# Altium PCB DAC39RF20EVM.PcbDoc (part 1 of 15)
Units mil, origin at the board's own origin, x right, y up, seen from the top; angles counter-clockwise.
Board outline 6200 x 2716.54 mil, 16 copper layers (Top Layer, L2 GND, L3 PWR, L4 GND, L5 PWR, L6 GND, L7 SIG, L8 GND, L9 GND, L10 SIG, L11 GND, L12 PWR, L13 GND, L14 PWR, L15 GND, Bottom Layer), stack 76.97 mil thick; 766 components, 495 nets, 3414 pads, 2373 vias.
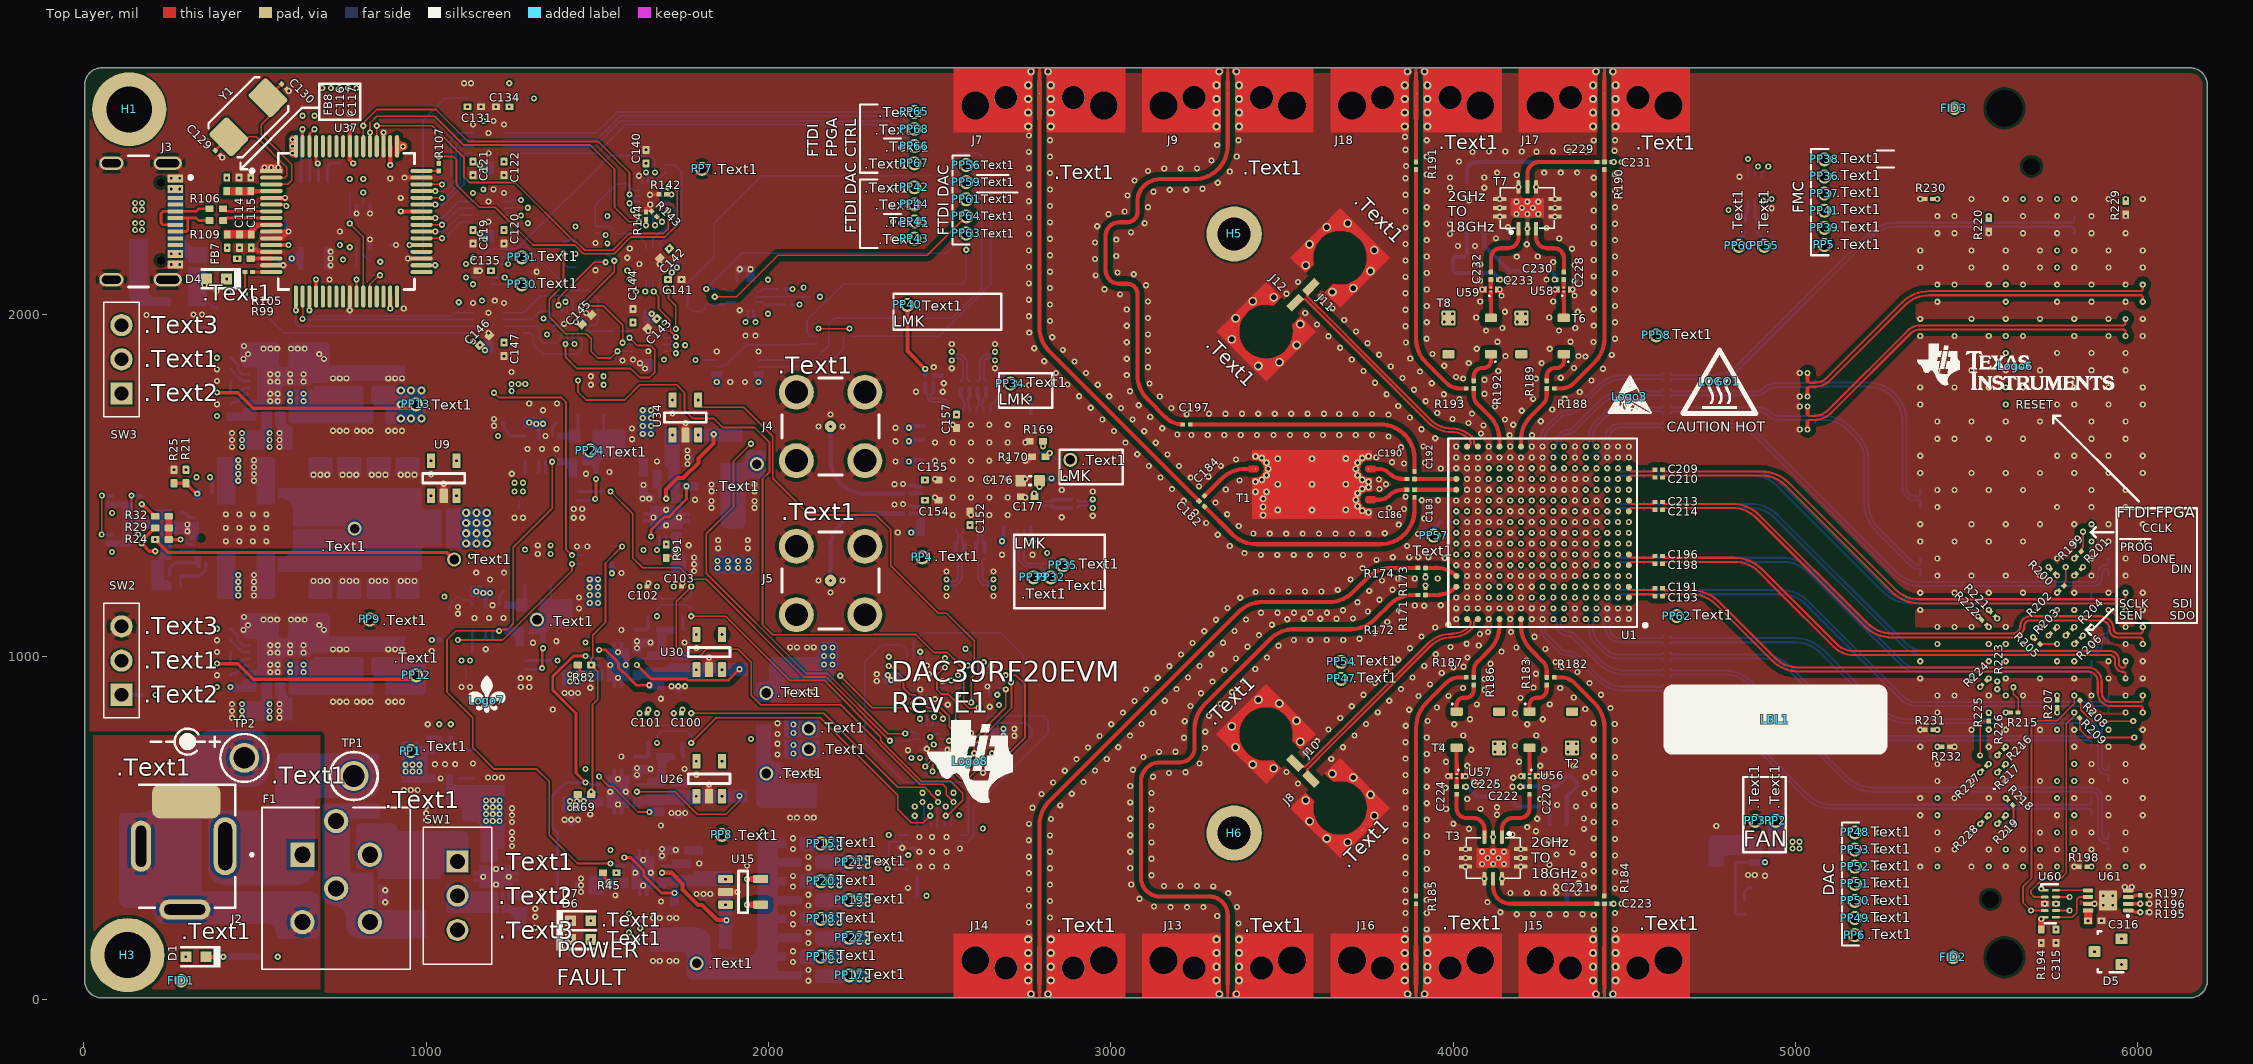
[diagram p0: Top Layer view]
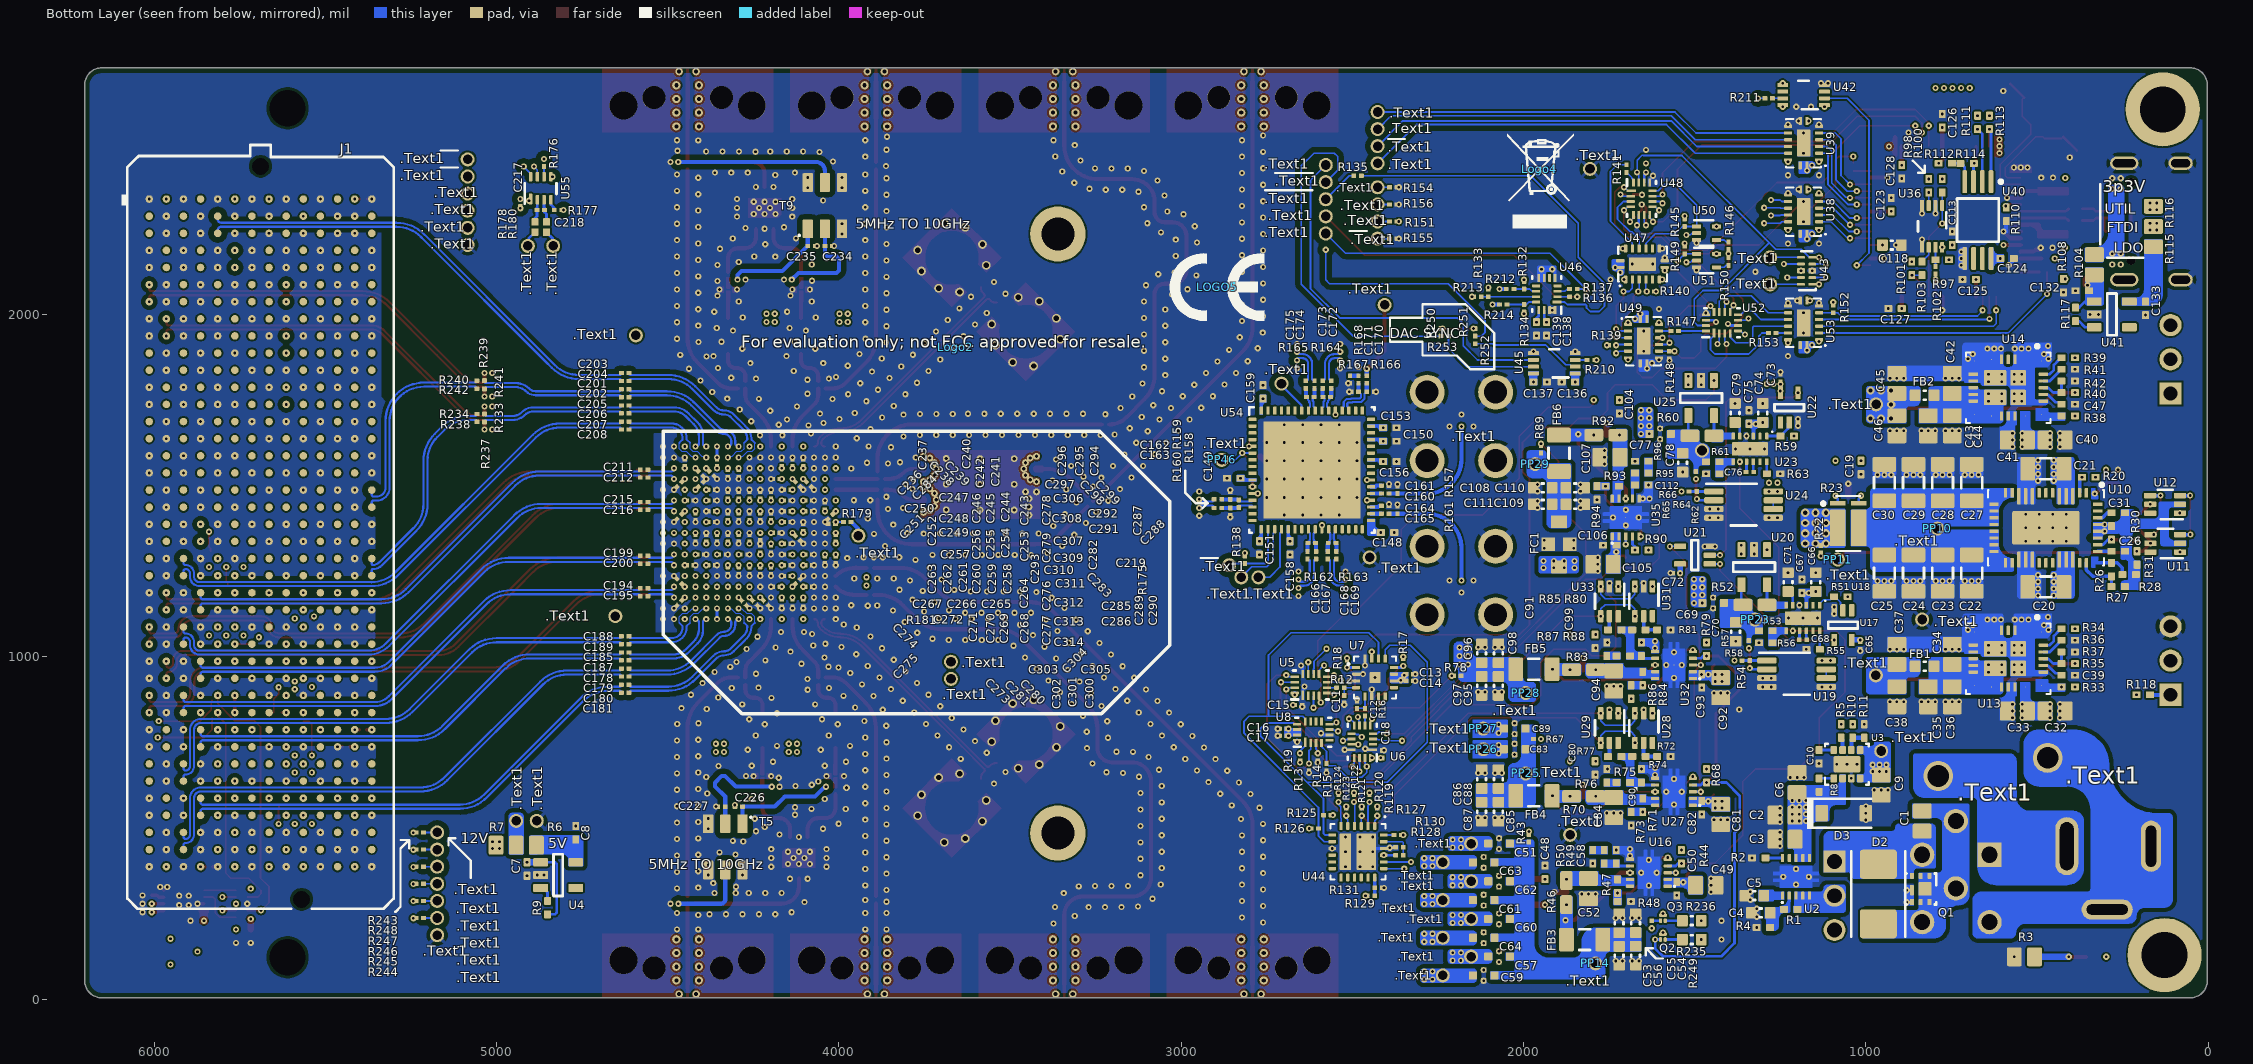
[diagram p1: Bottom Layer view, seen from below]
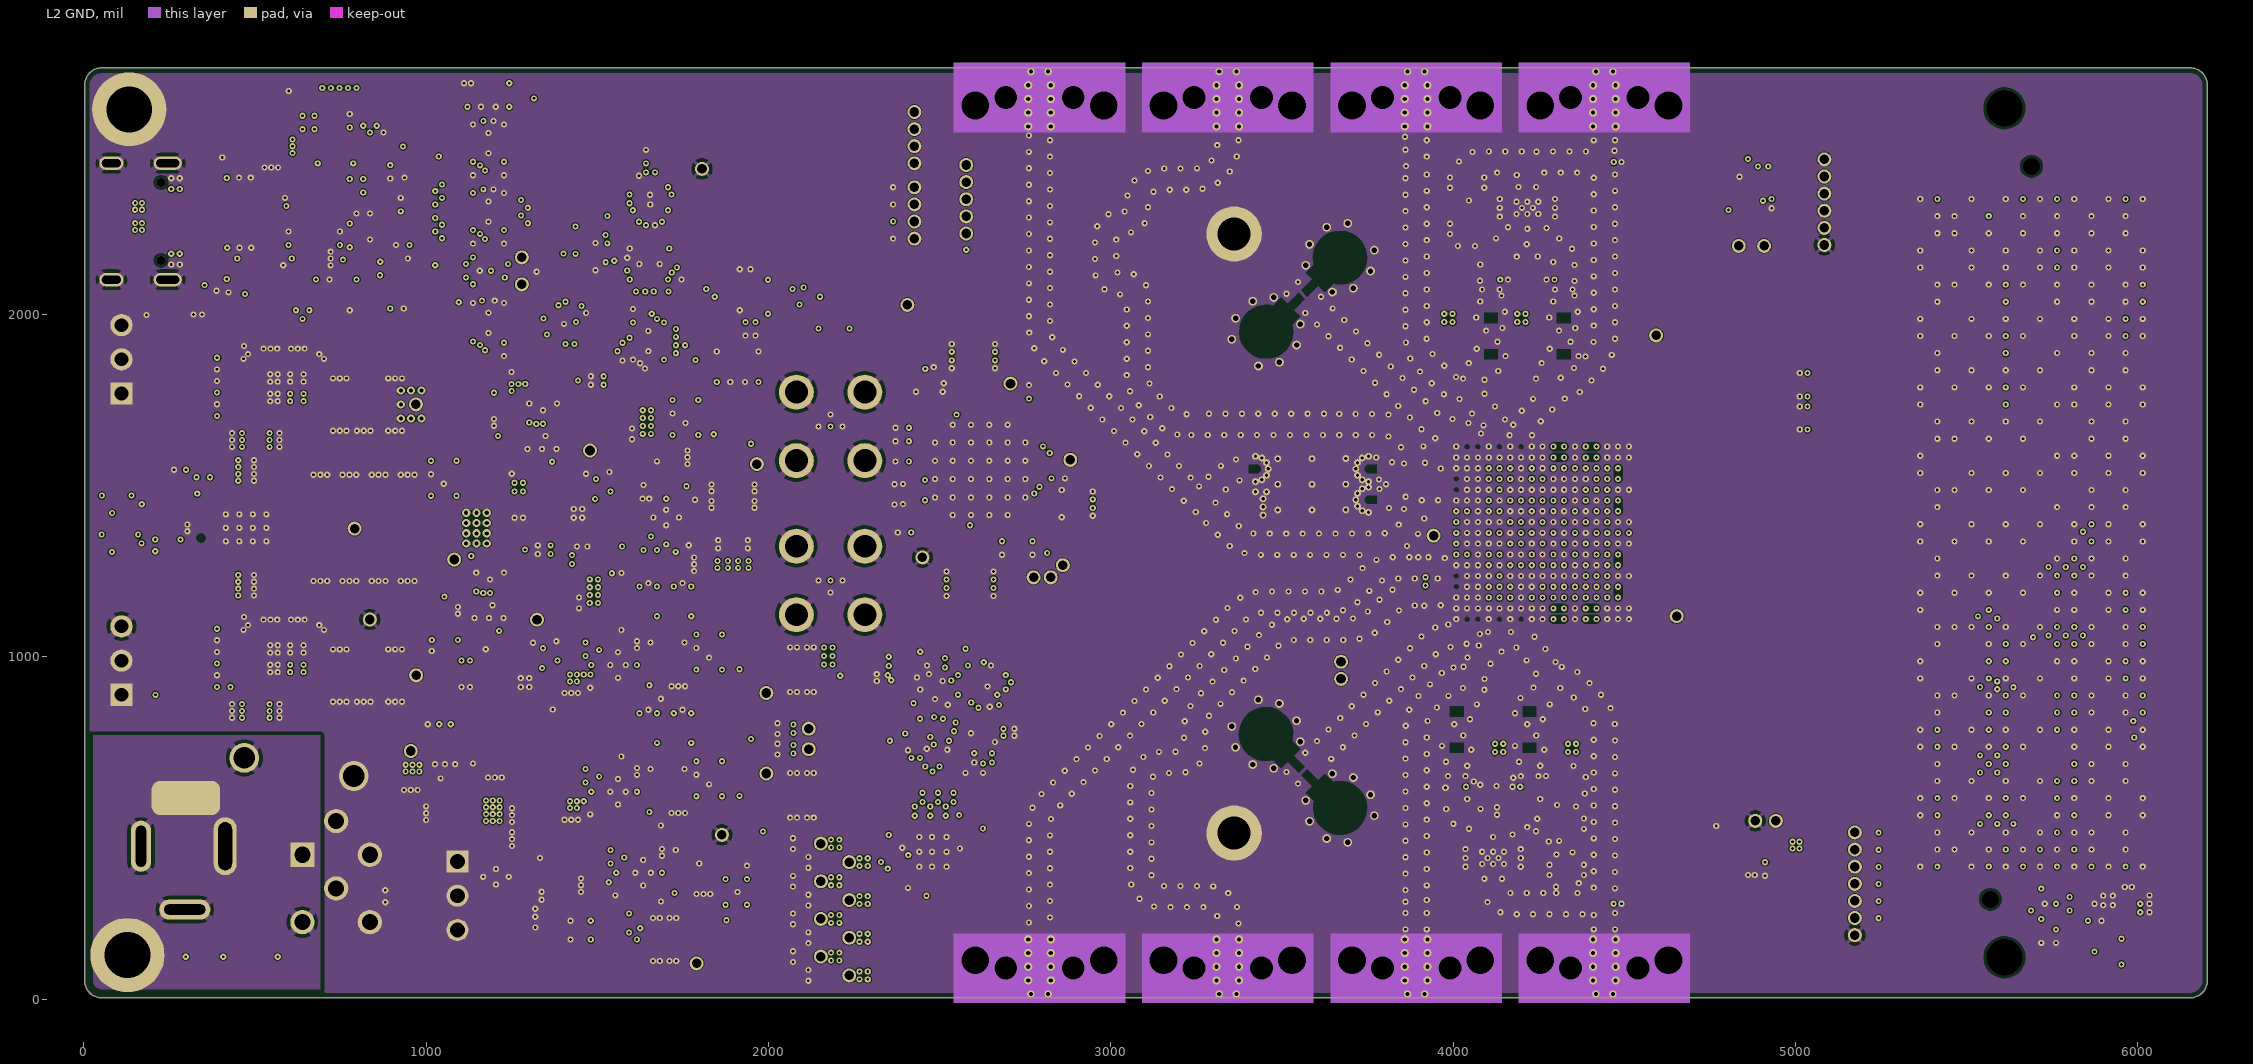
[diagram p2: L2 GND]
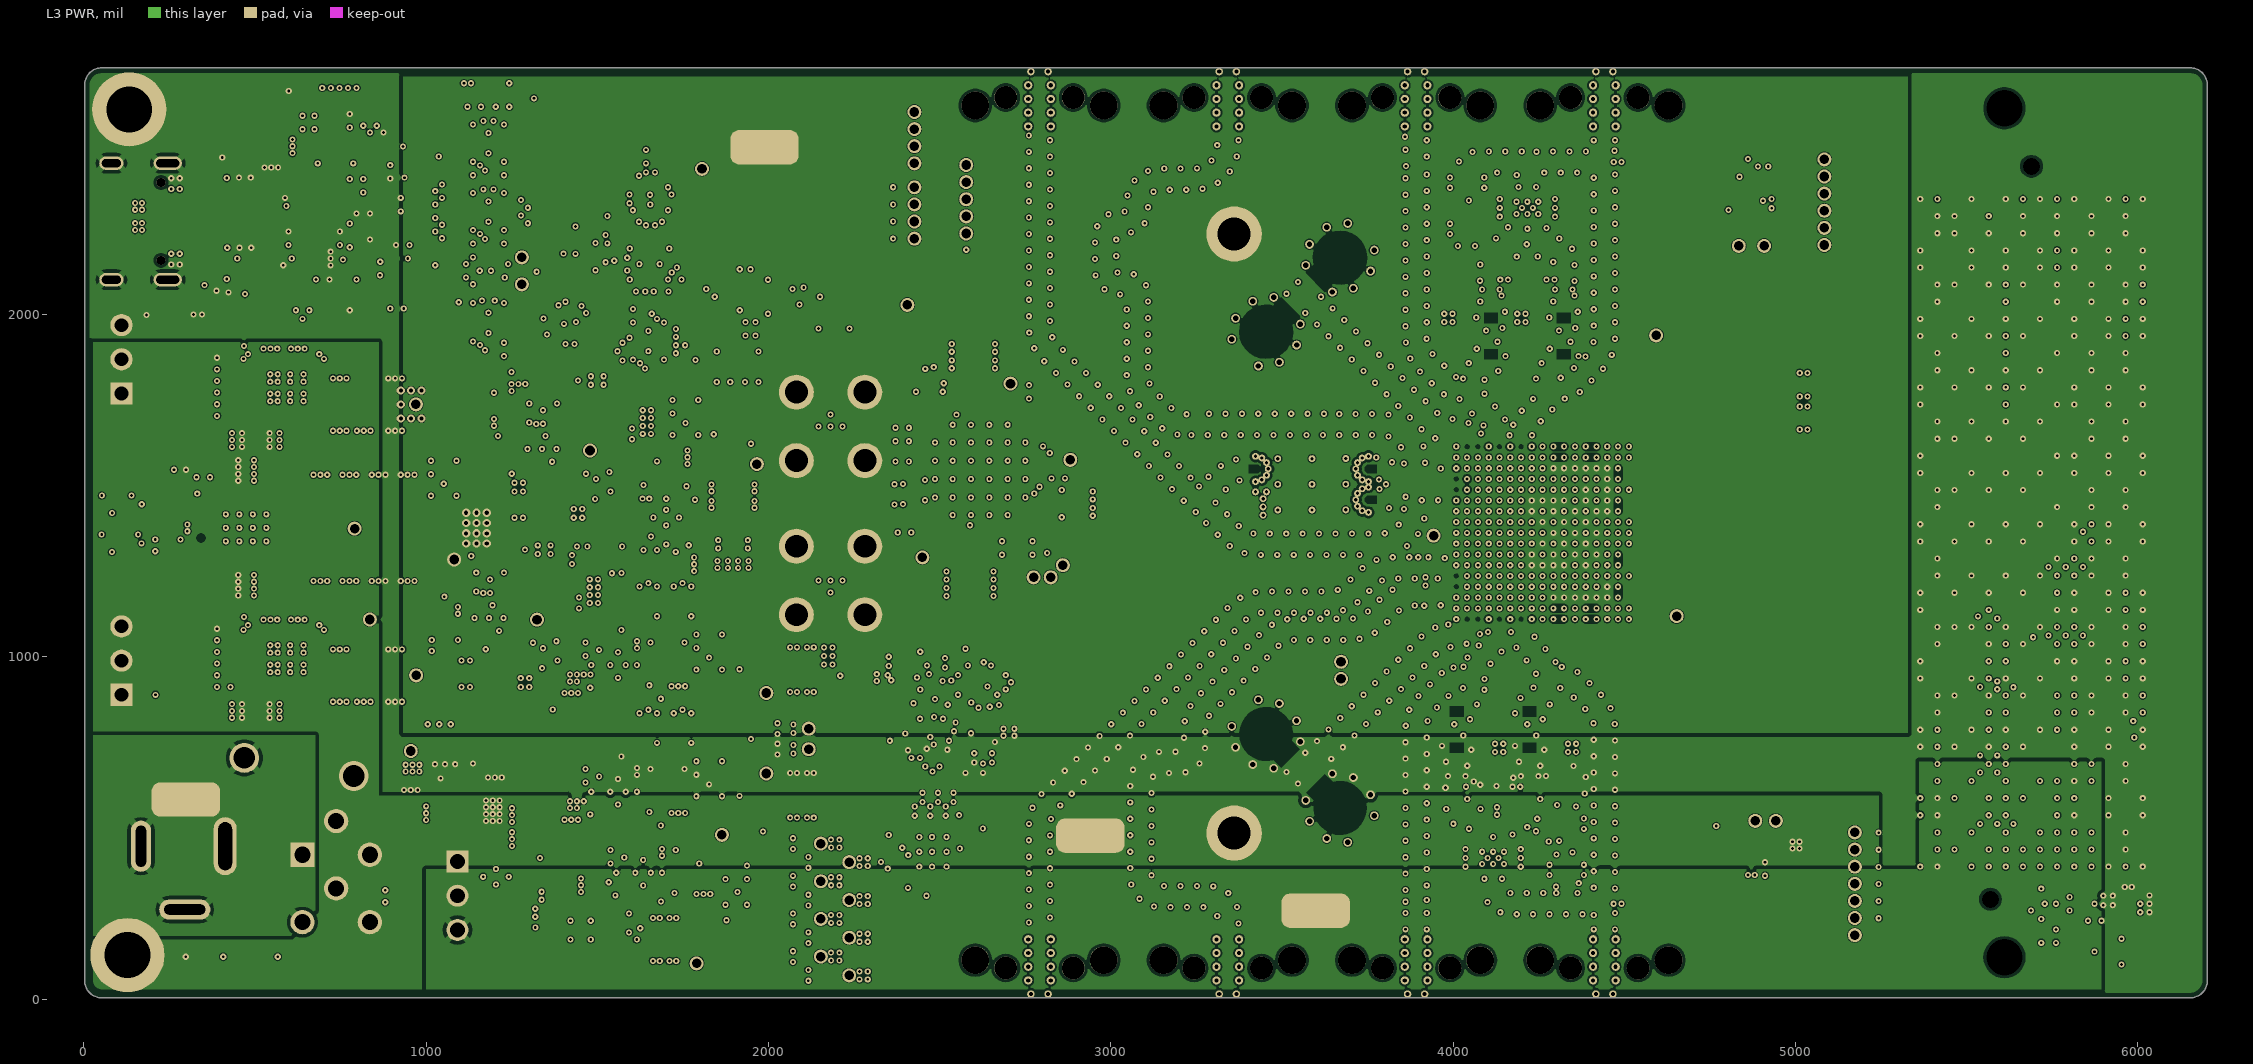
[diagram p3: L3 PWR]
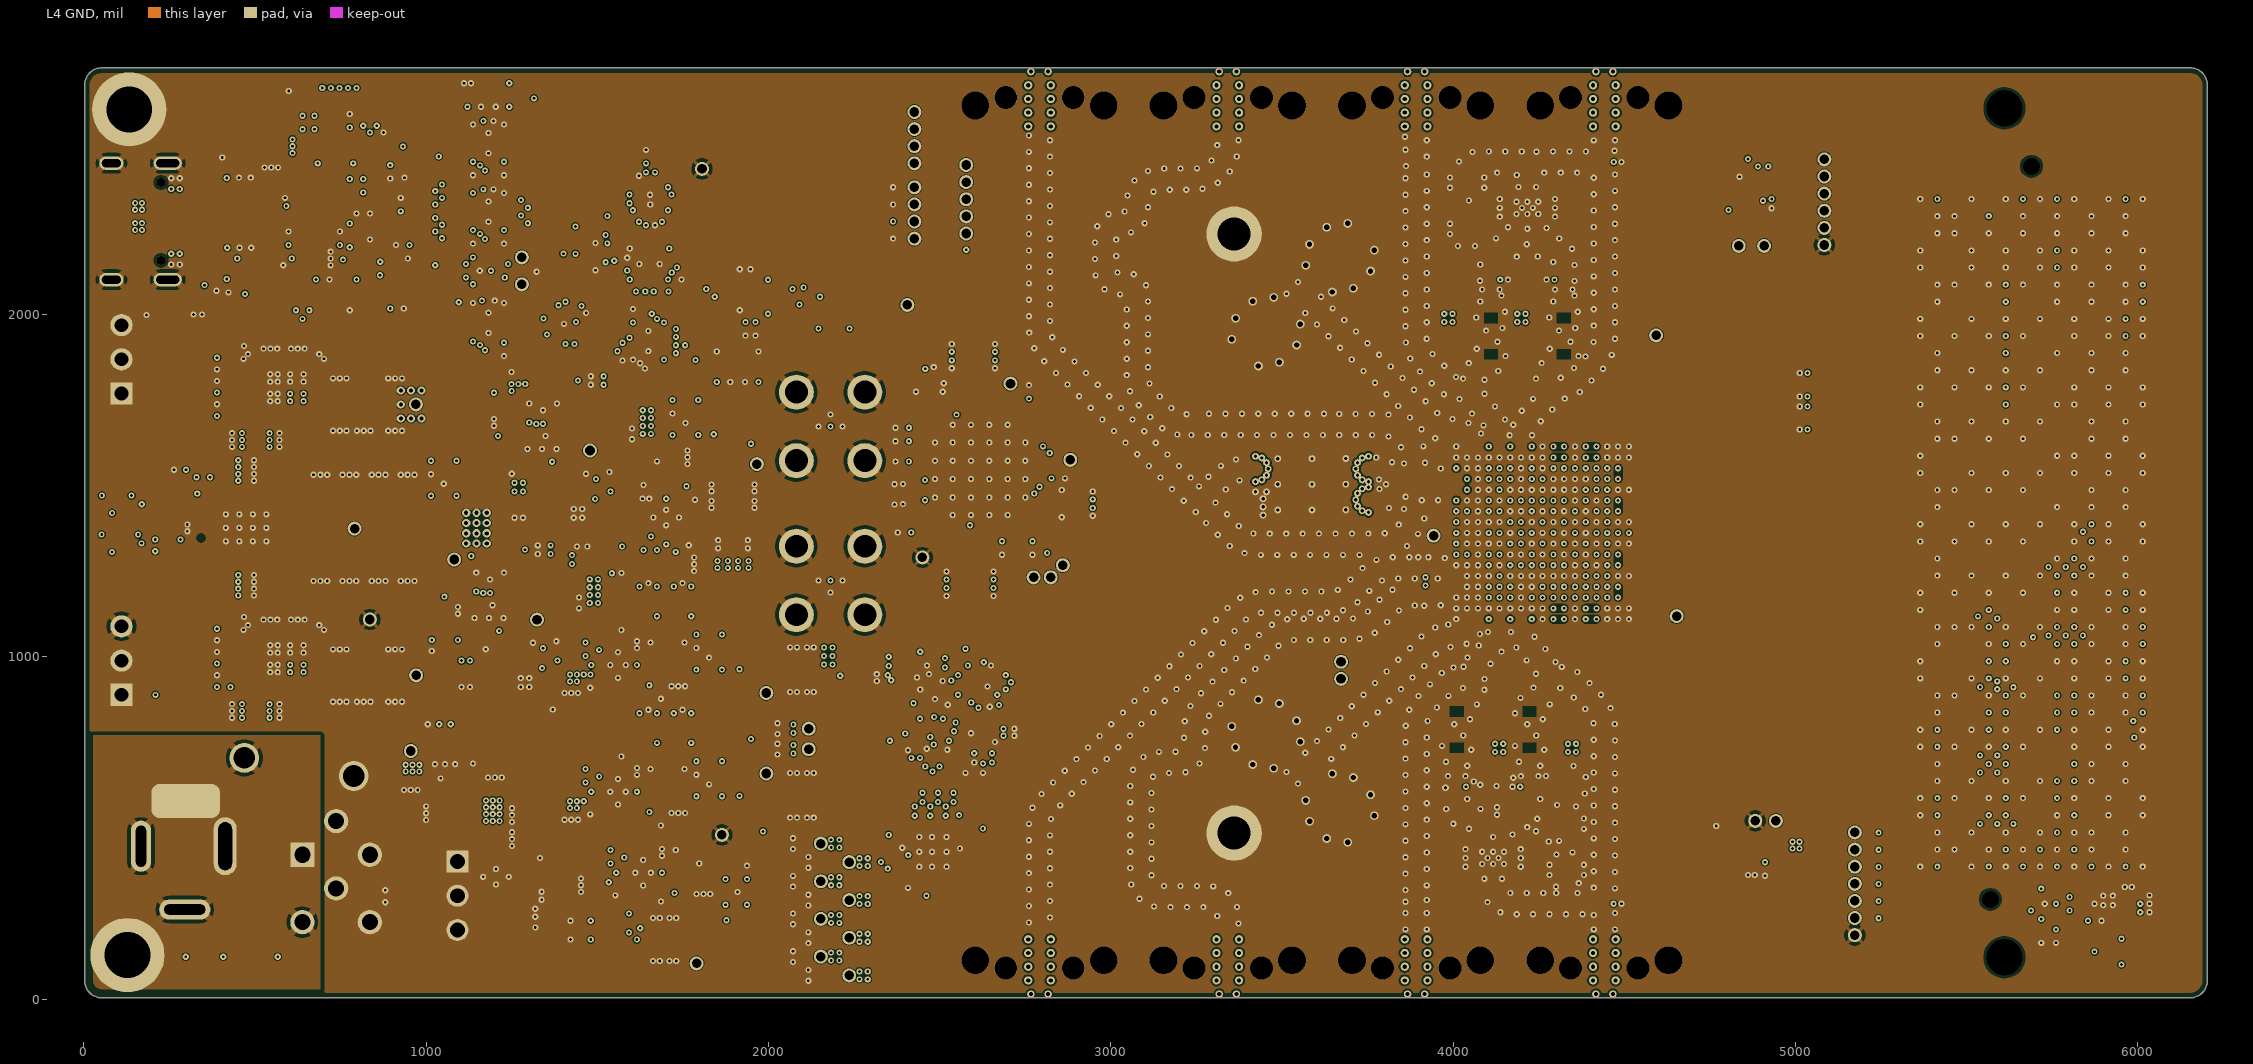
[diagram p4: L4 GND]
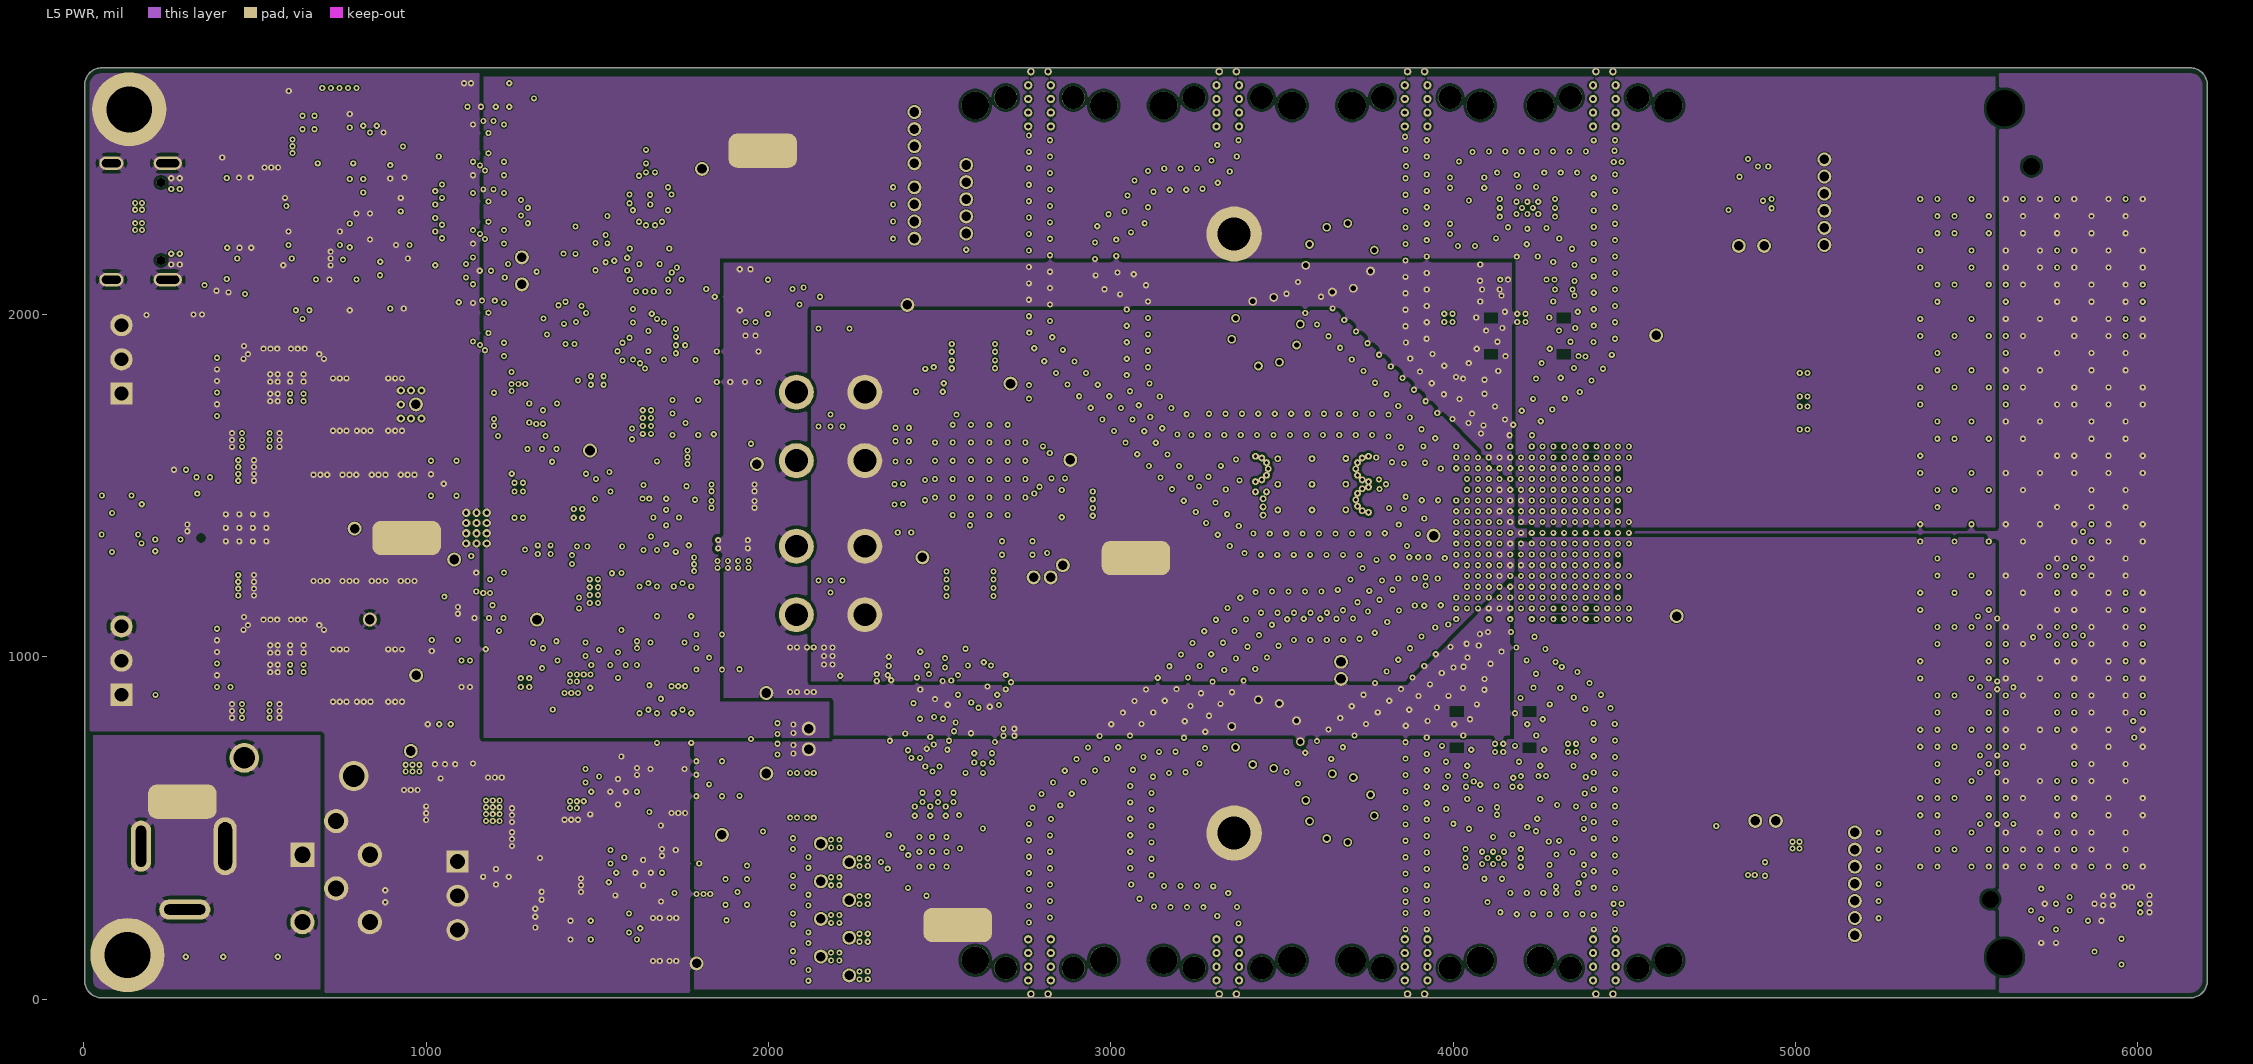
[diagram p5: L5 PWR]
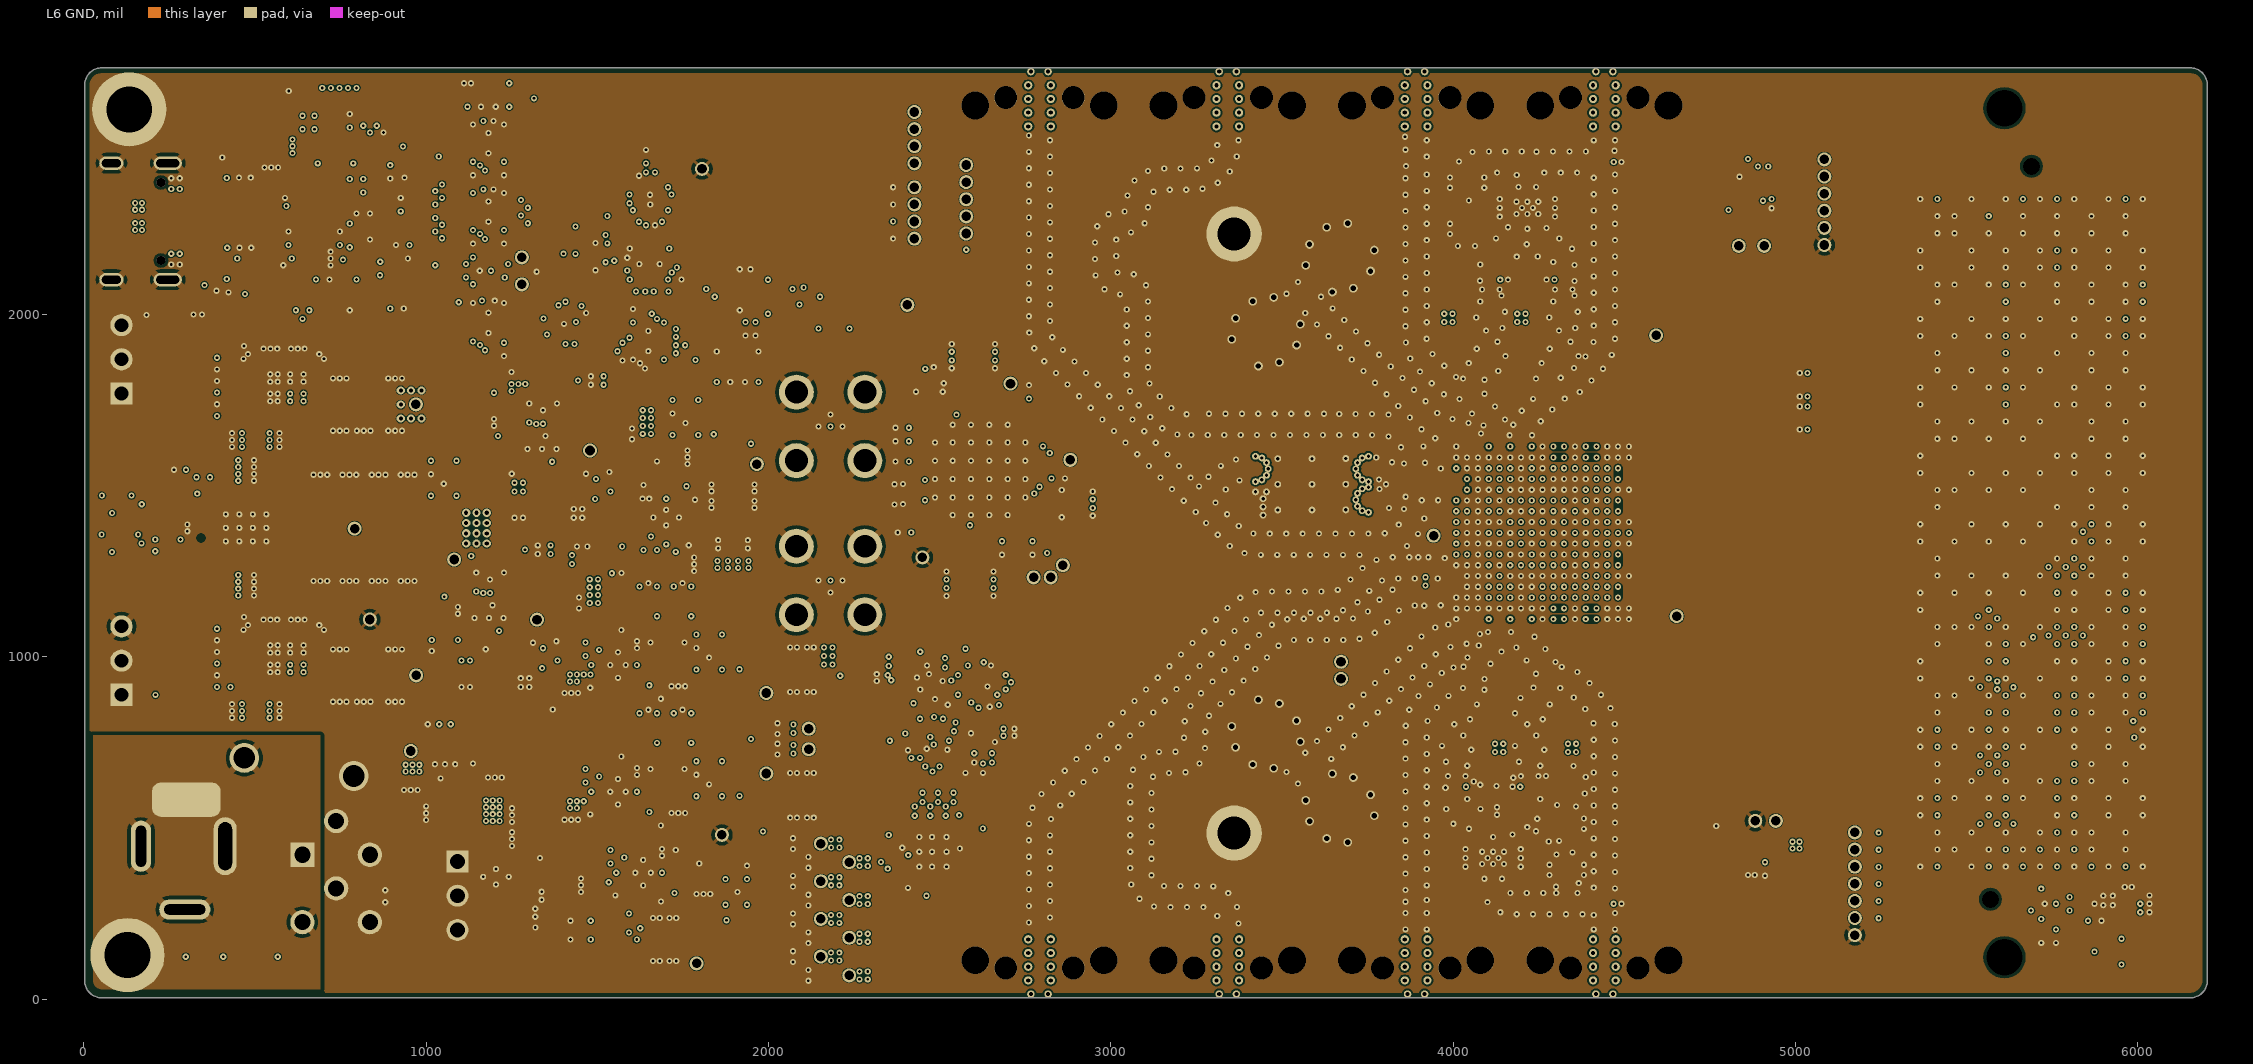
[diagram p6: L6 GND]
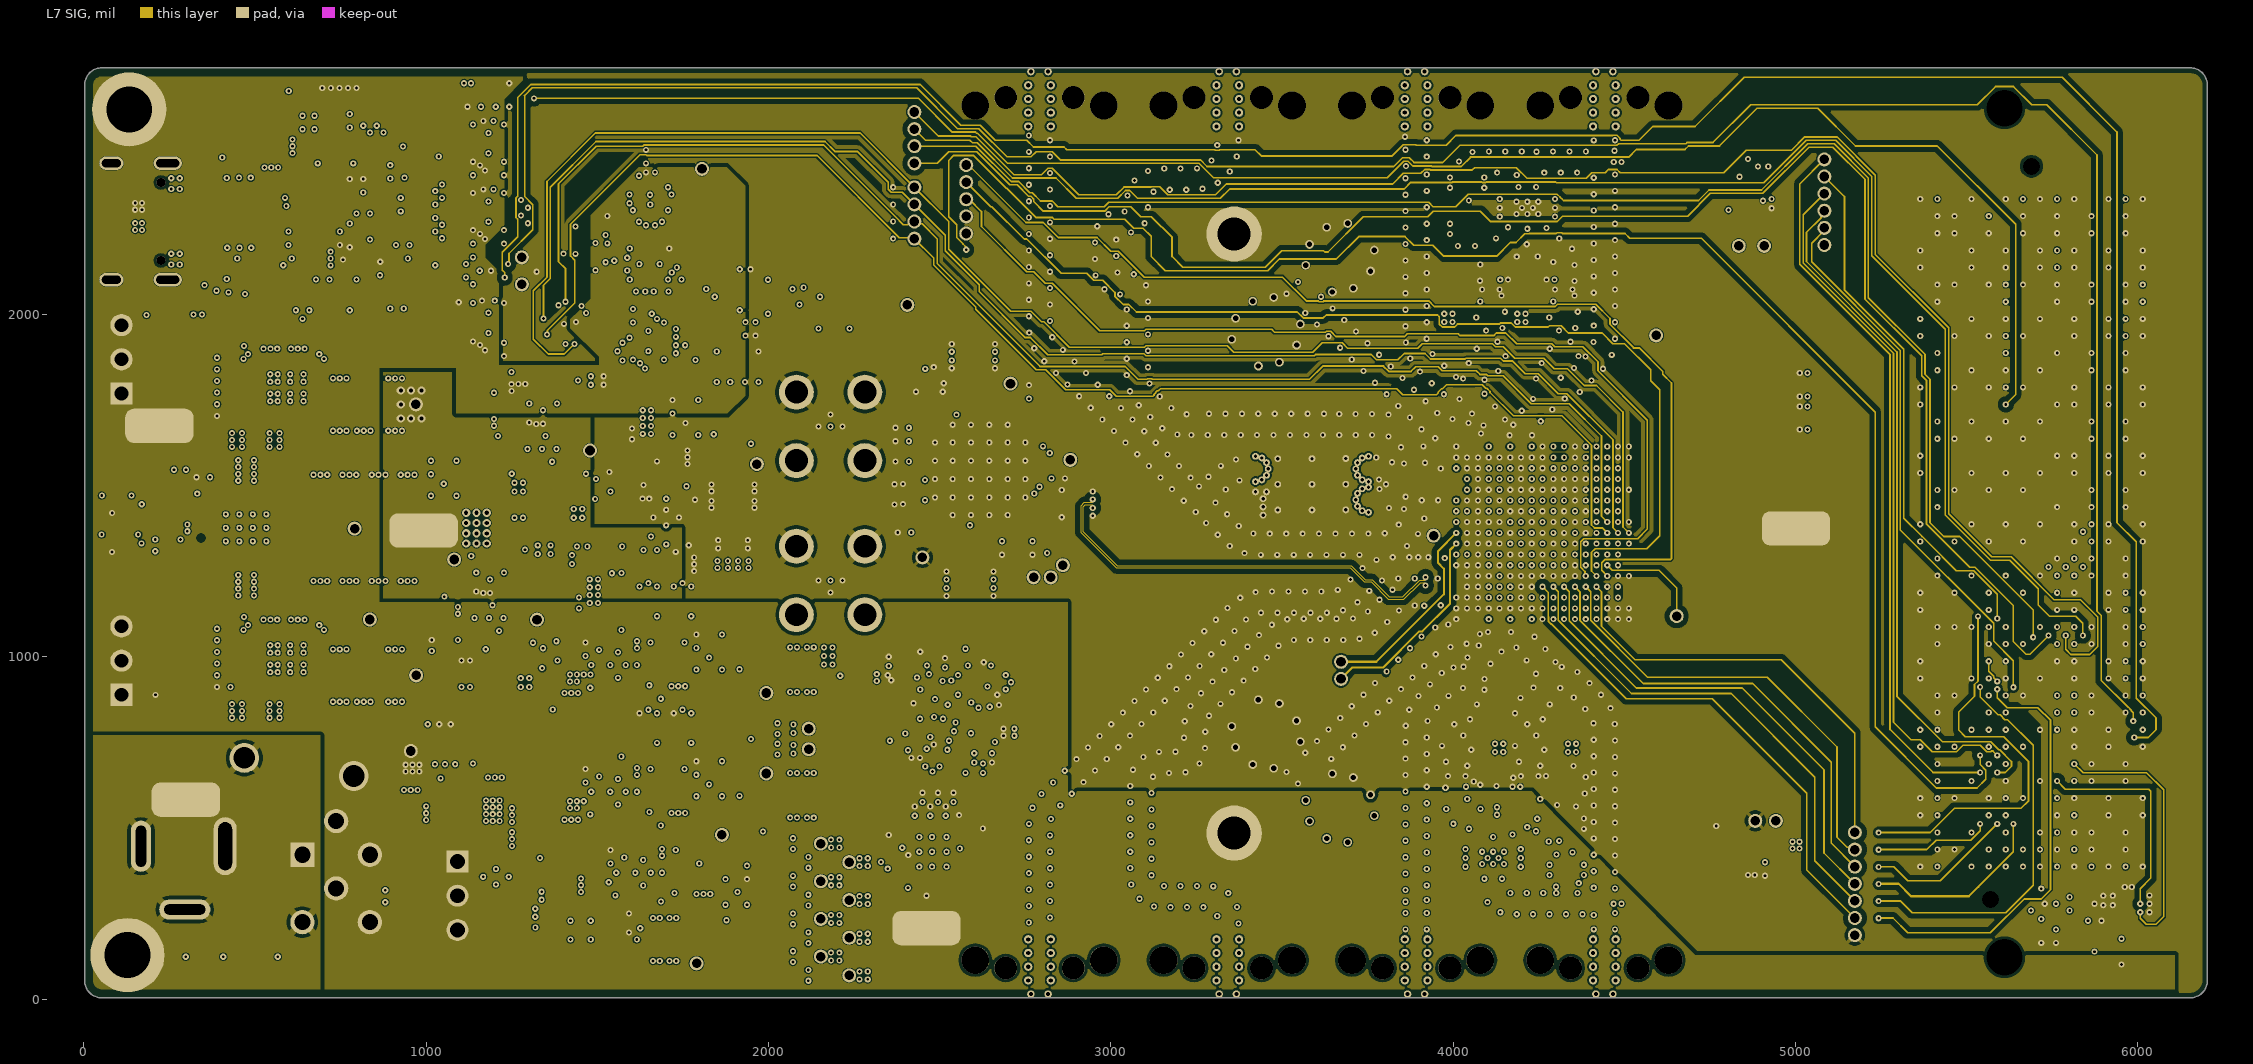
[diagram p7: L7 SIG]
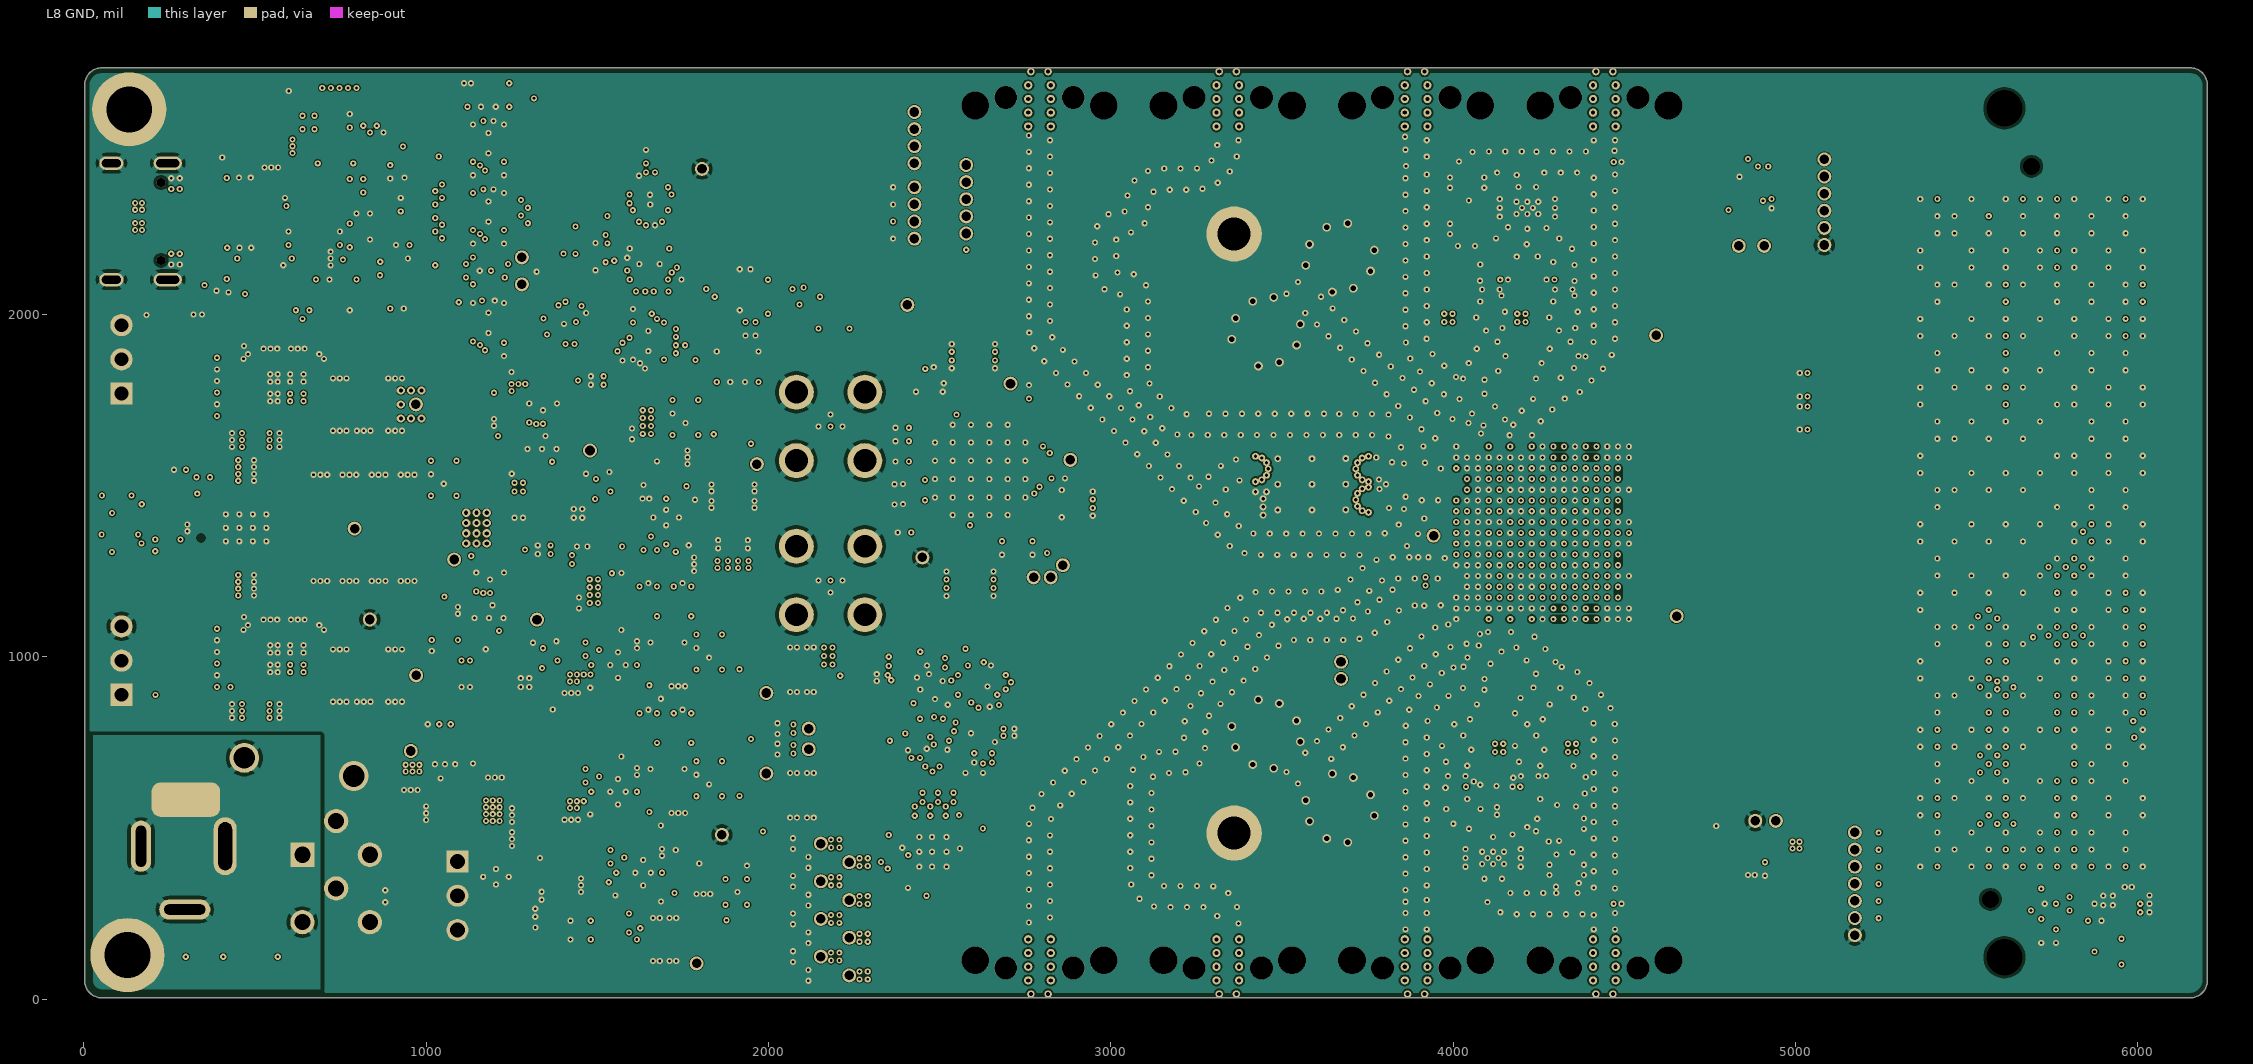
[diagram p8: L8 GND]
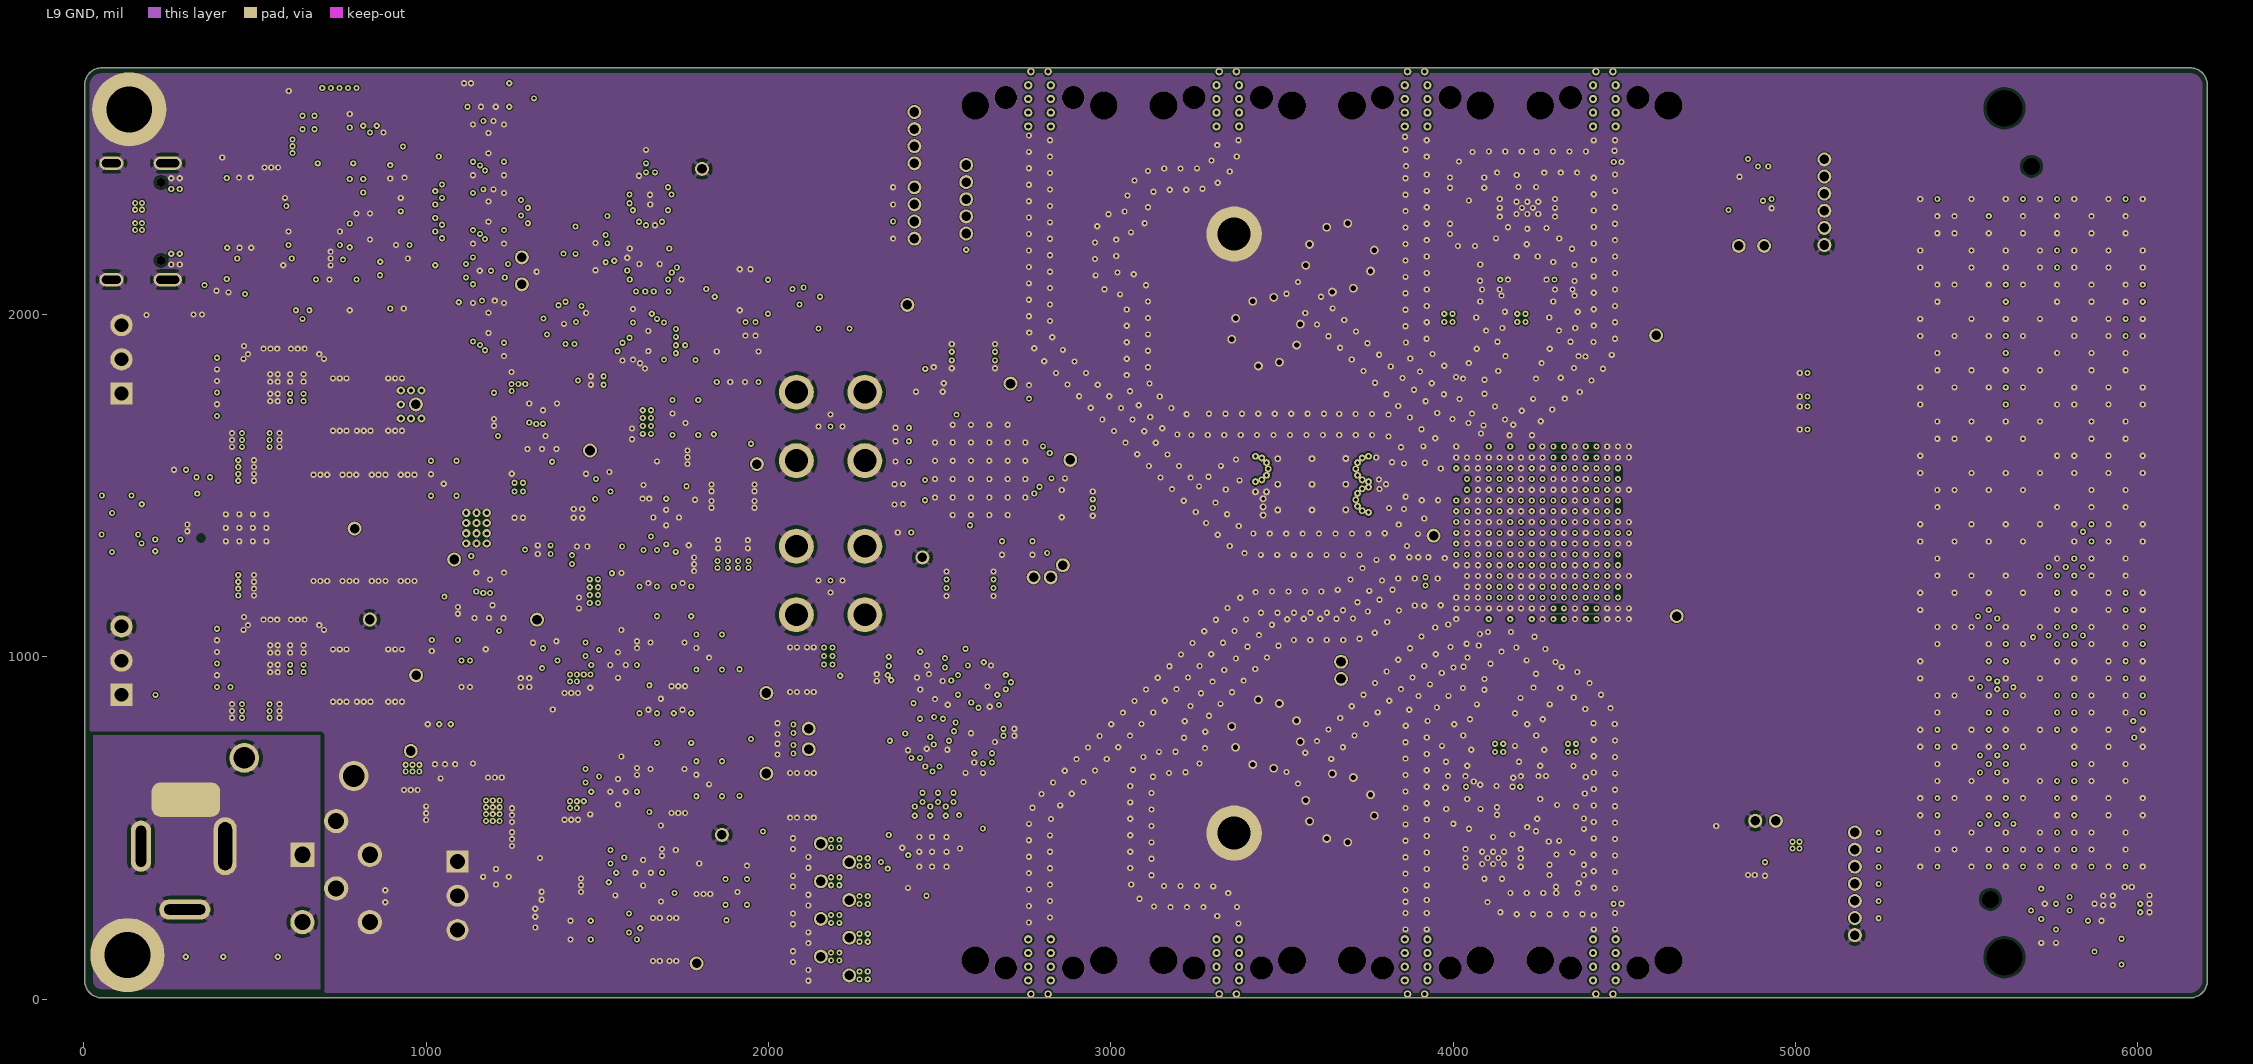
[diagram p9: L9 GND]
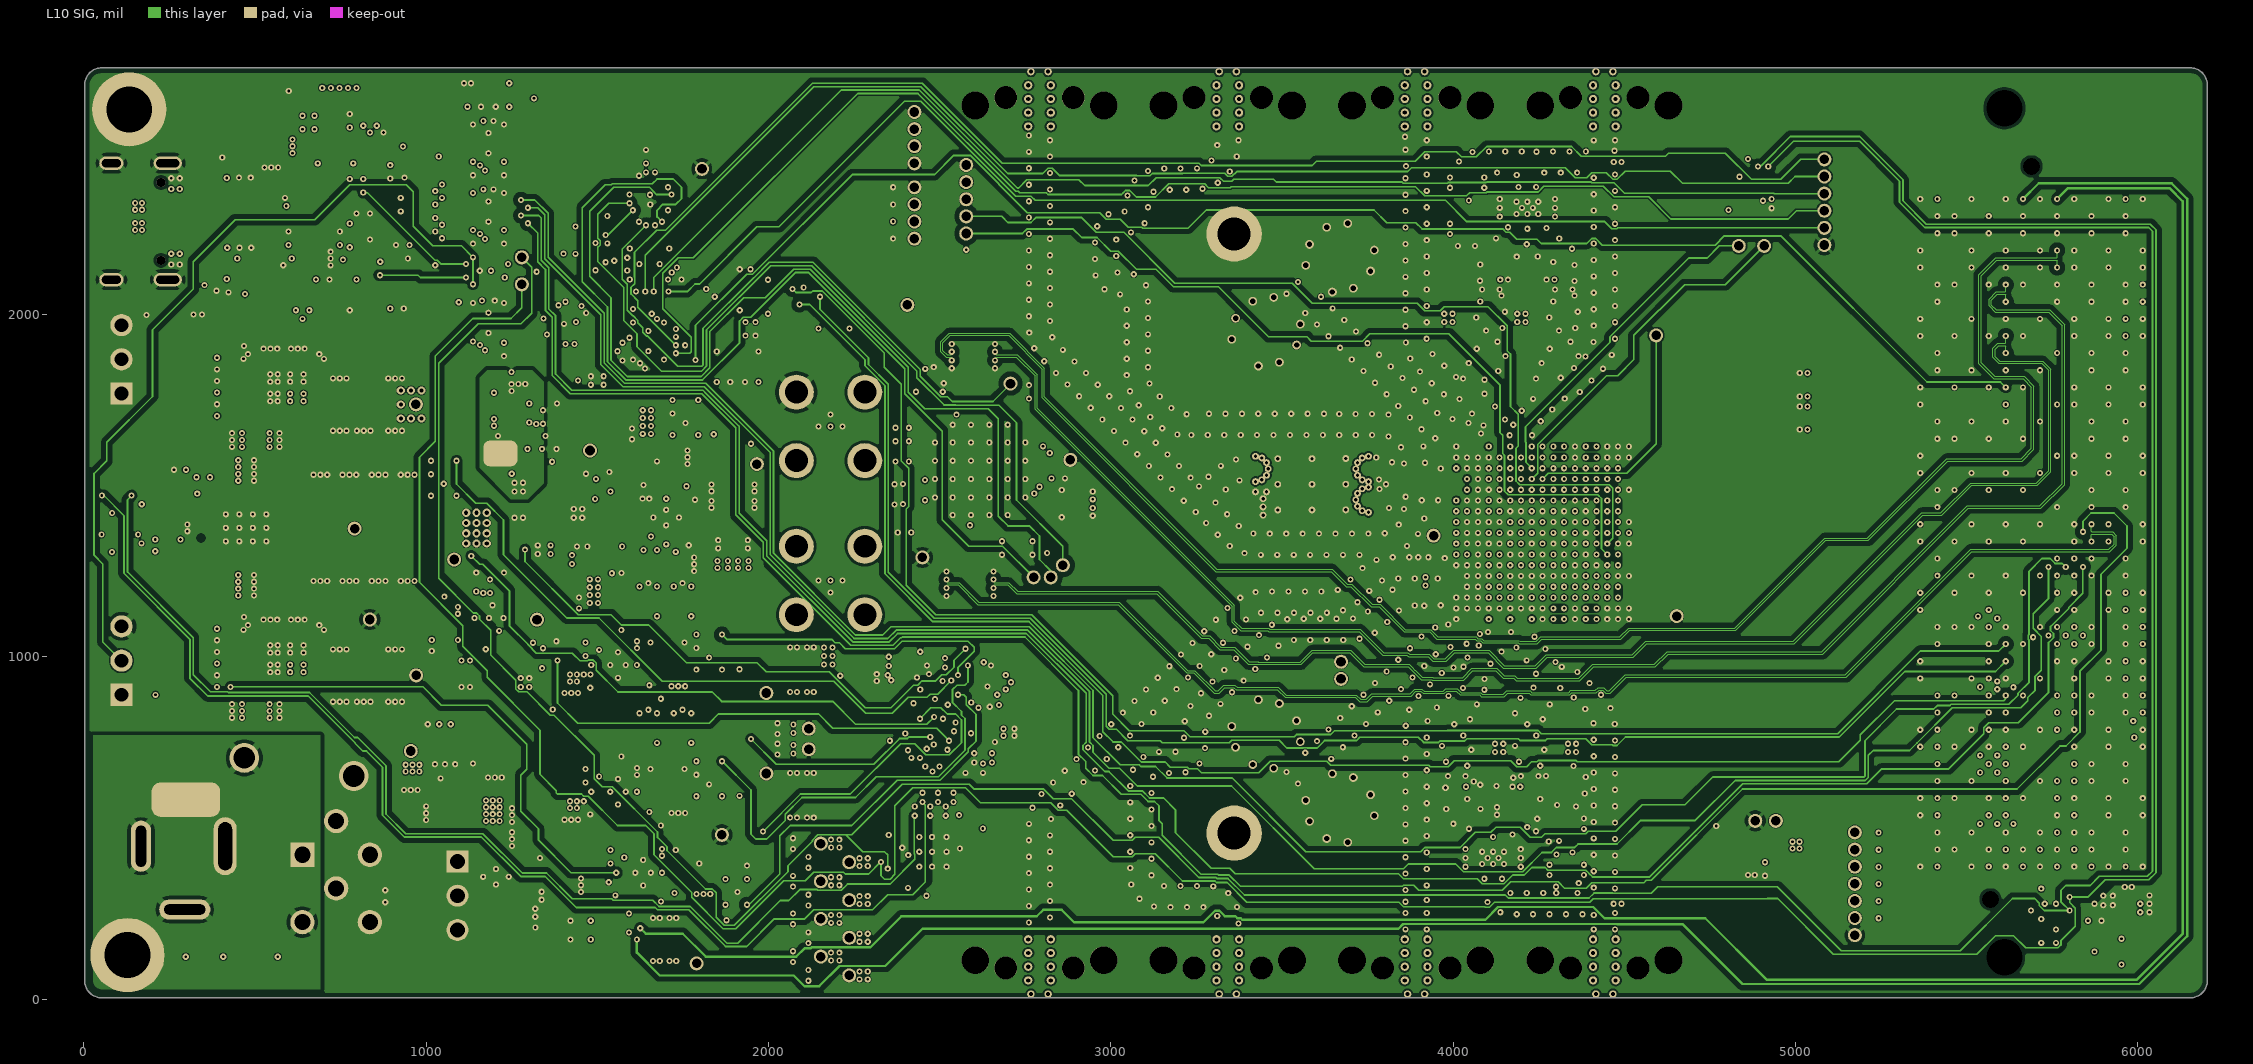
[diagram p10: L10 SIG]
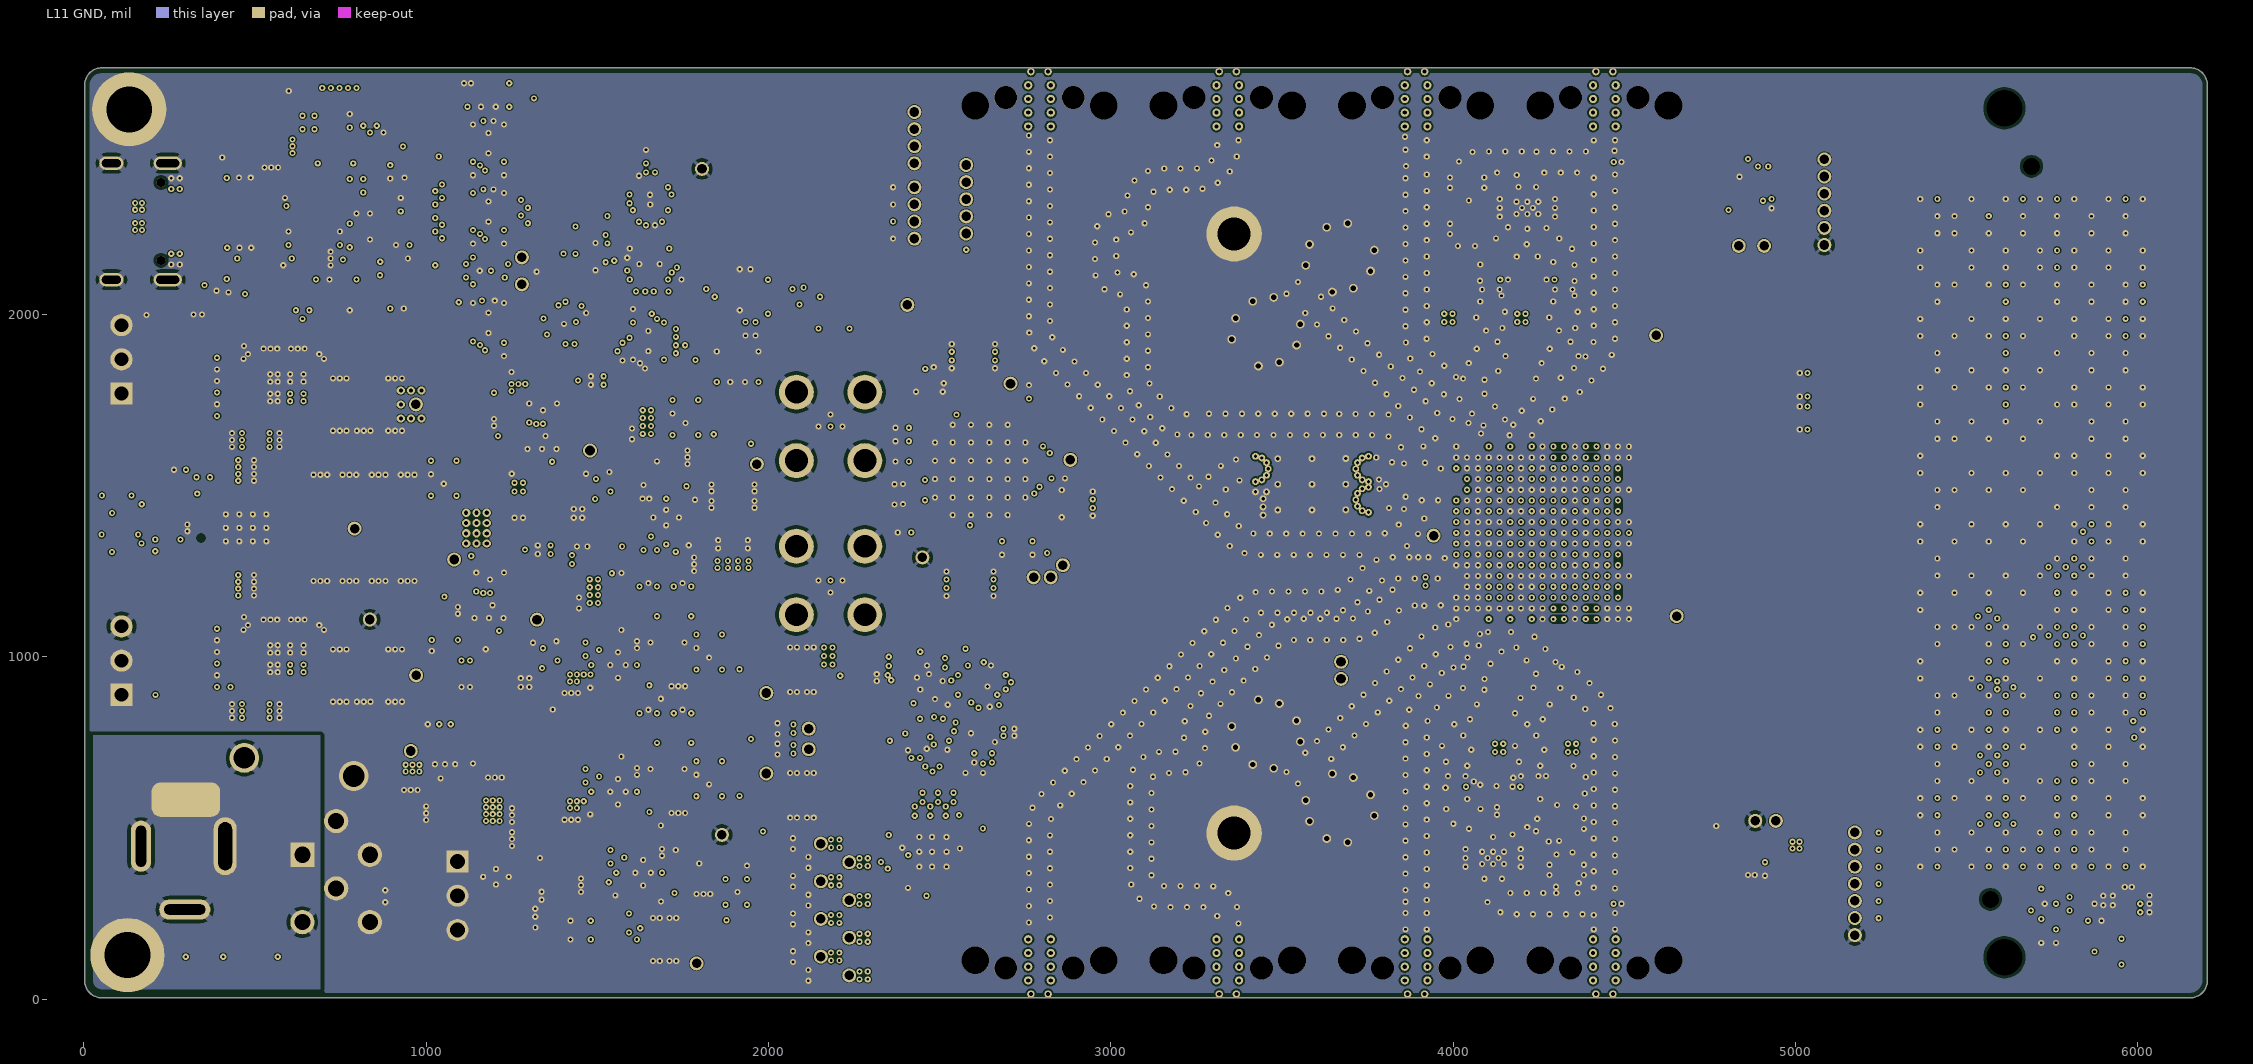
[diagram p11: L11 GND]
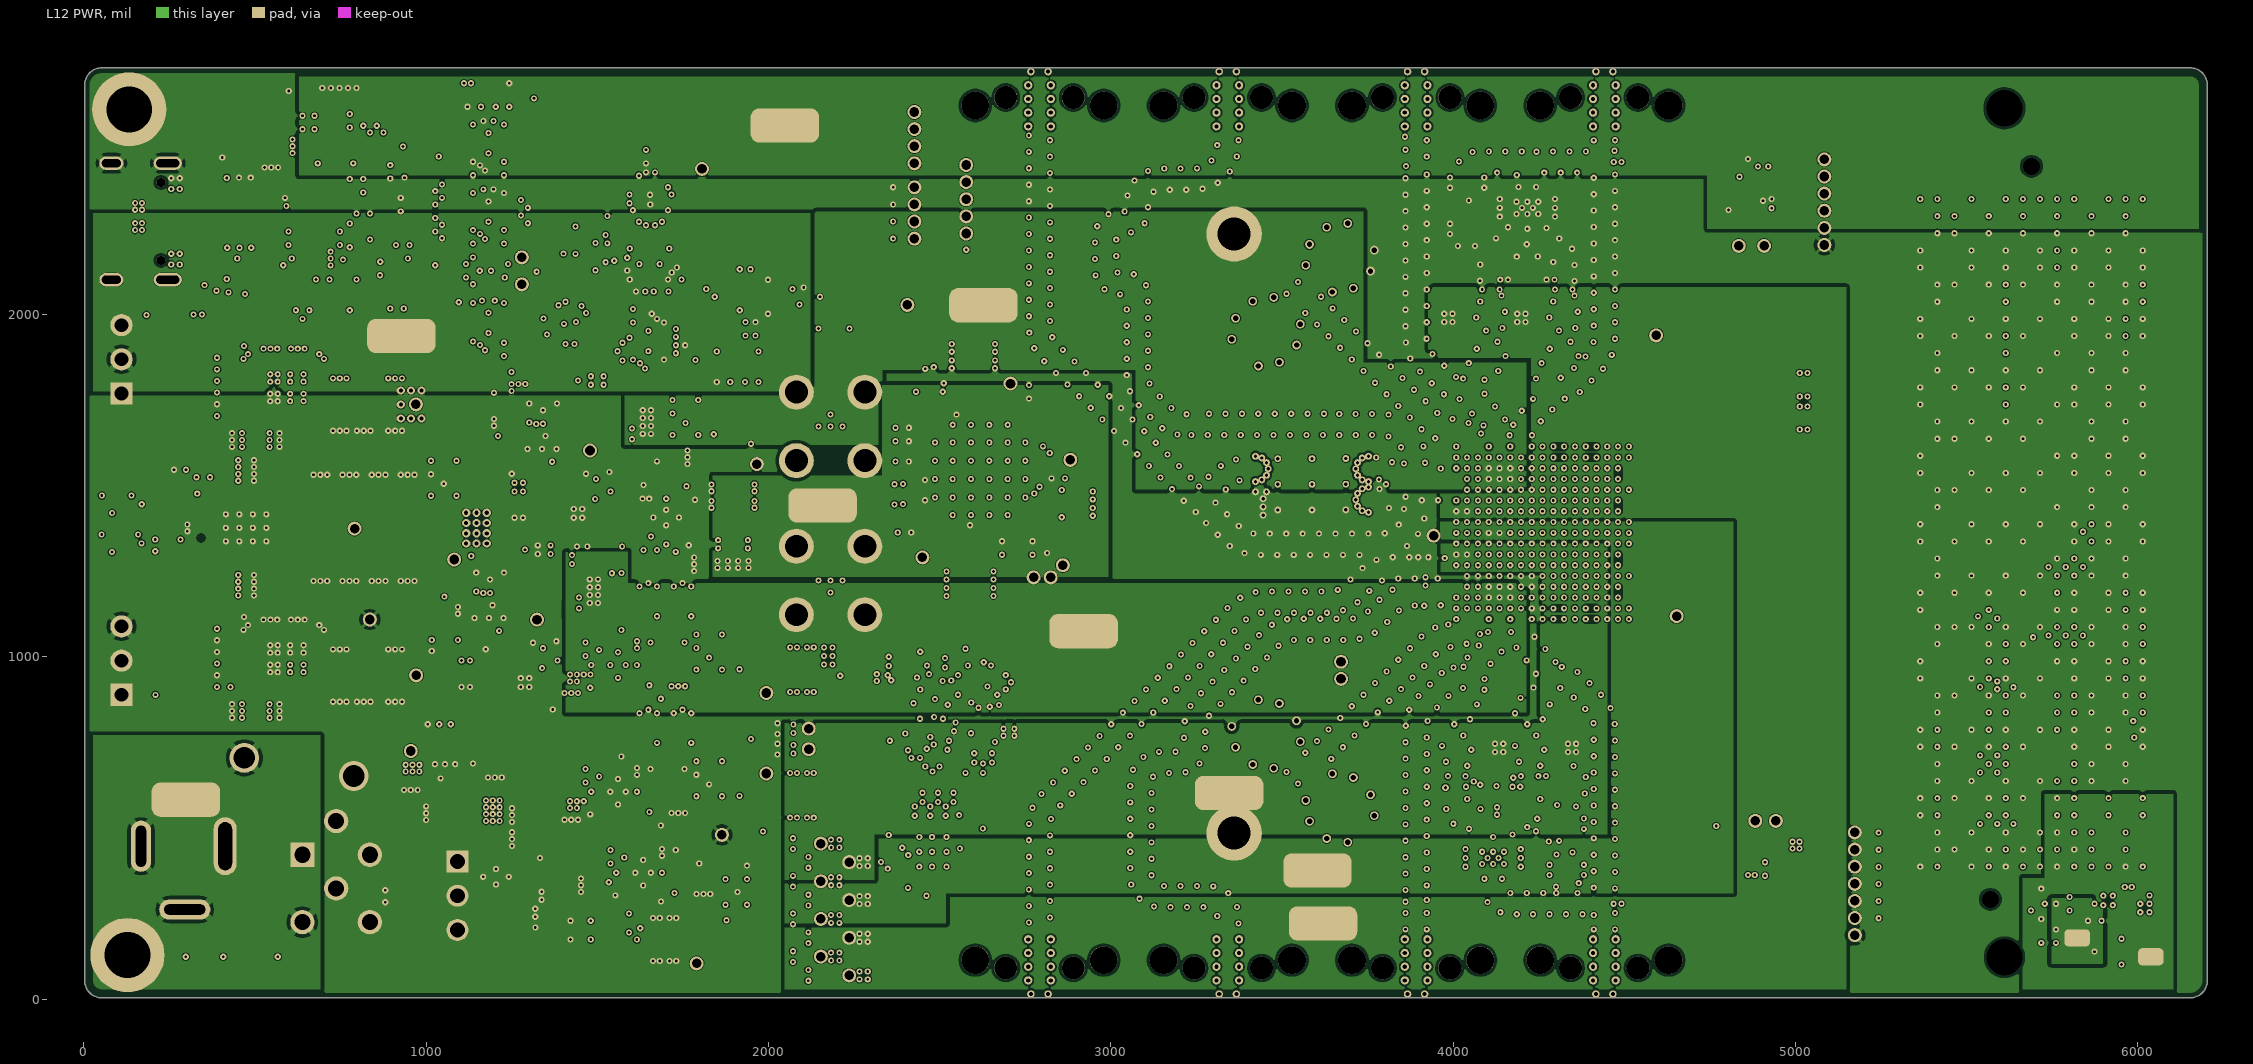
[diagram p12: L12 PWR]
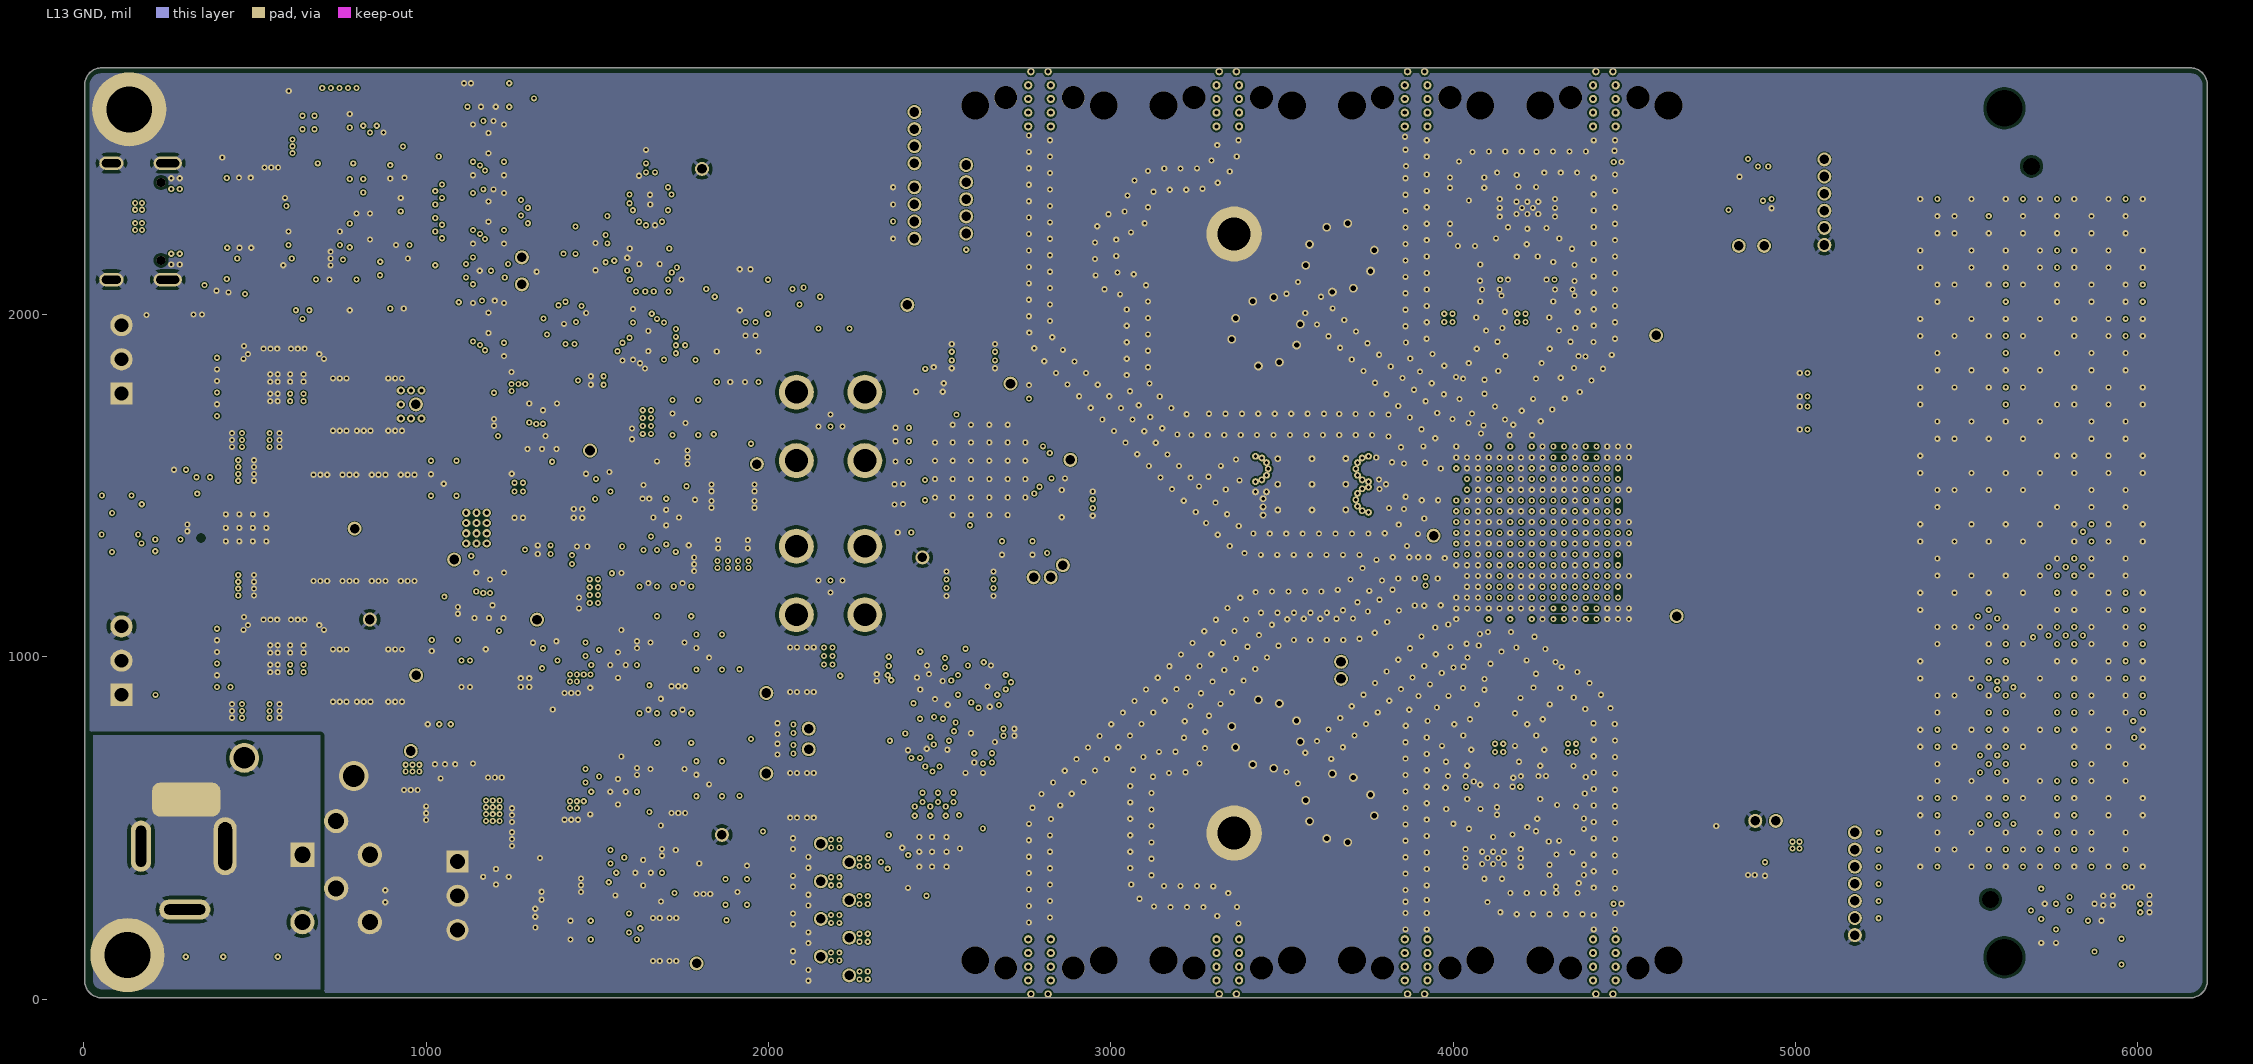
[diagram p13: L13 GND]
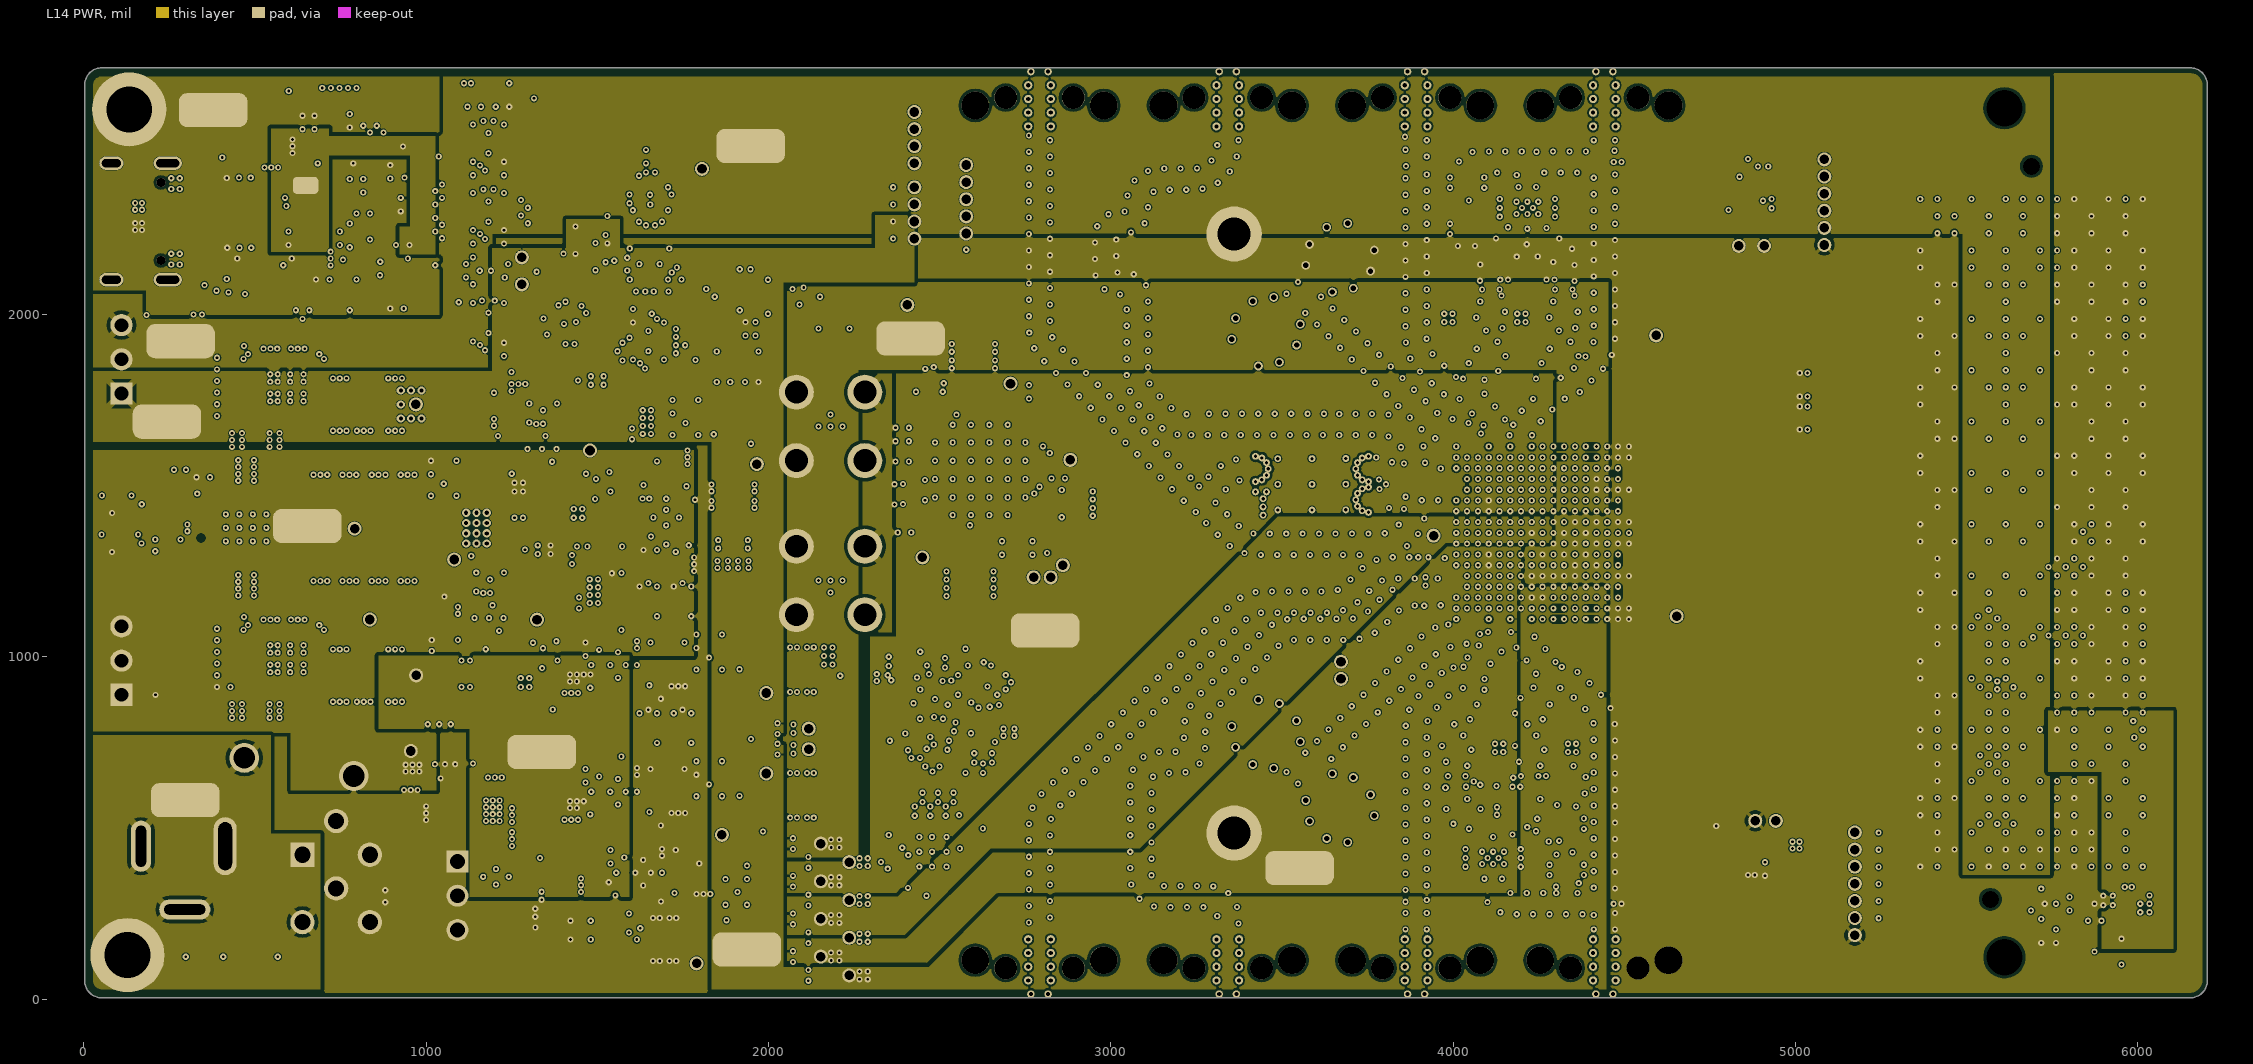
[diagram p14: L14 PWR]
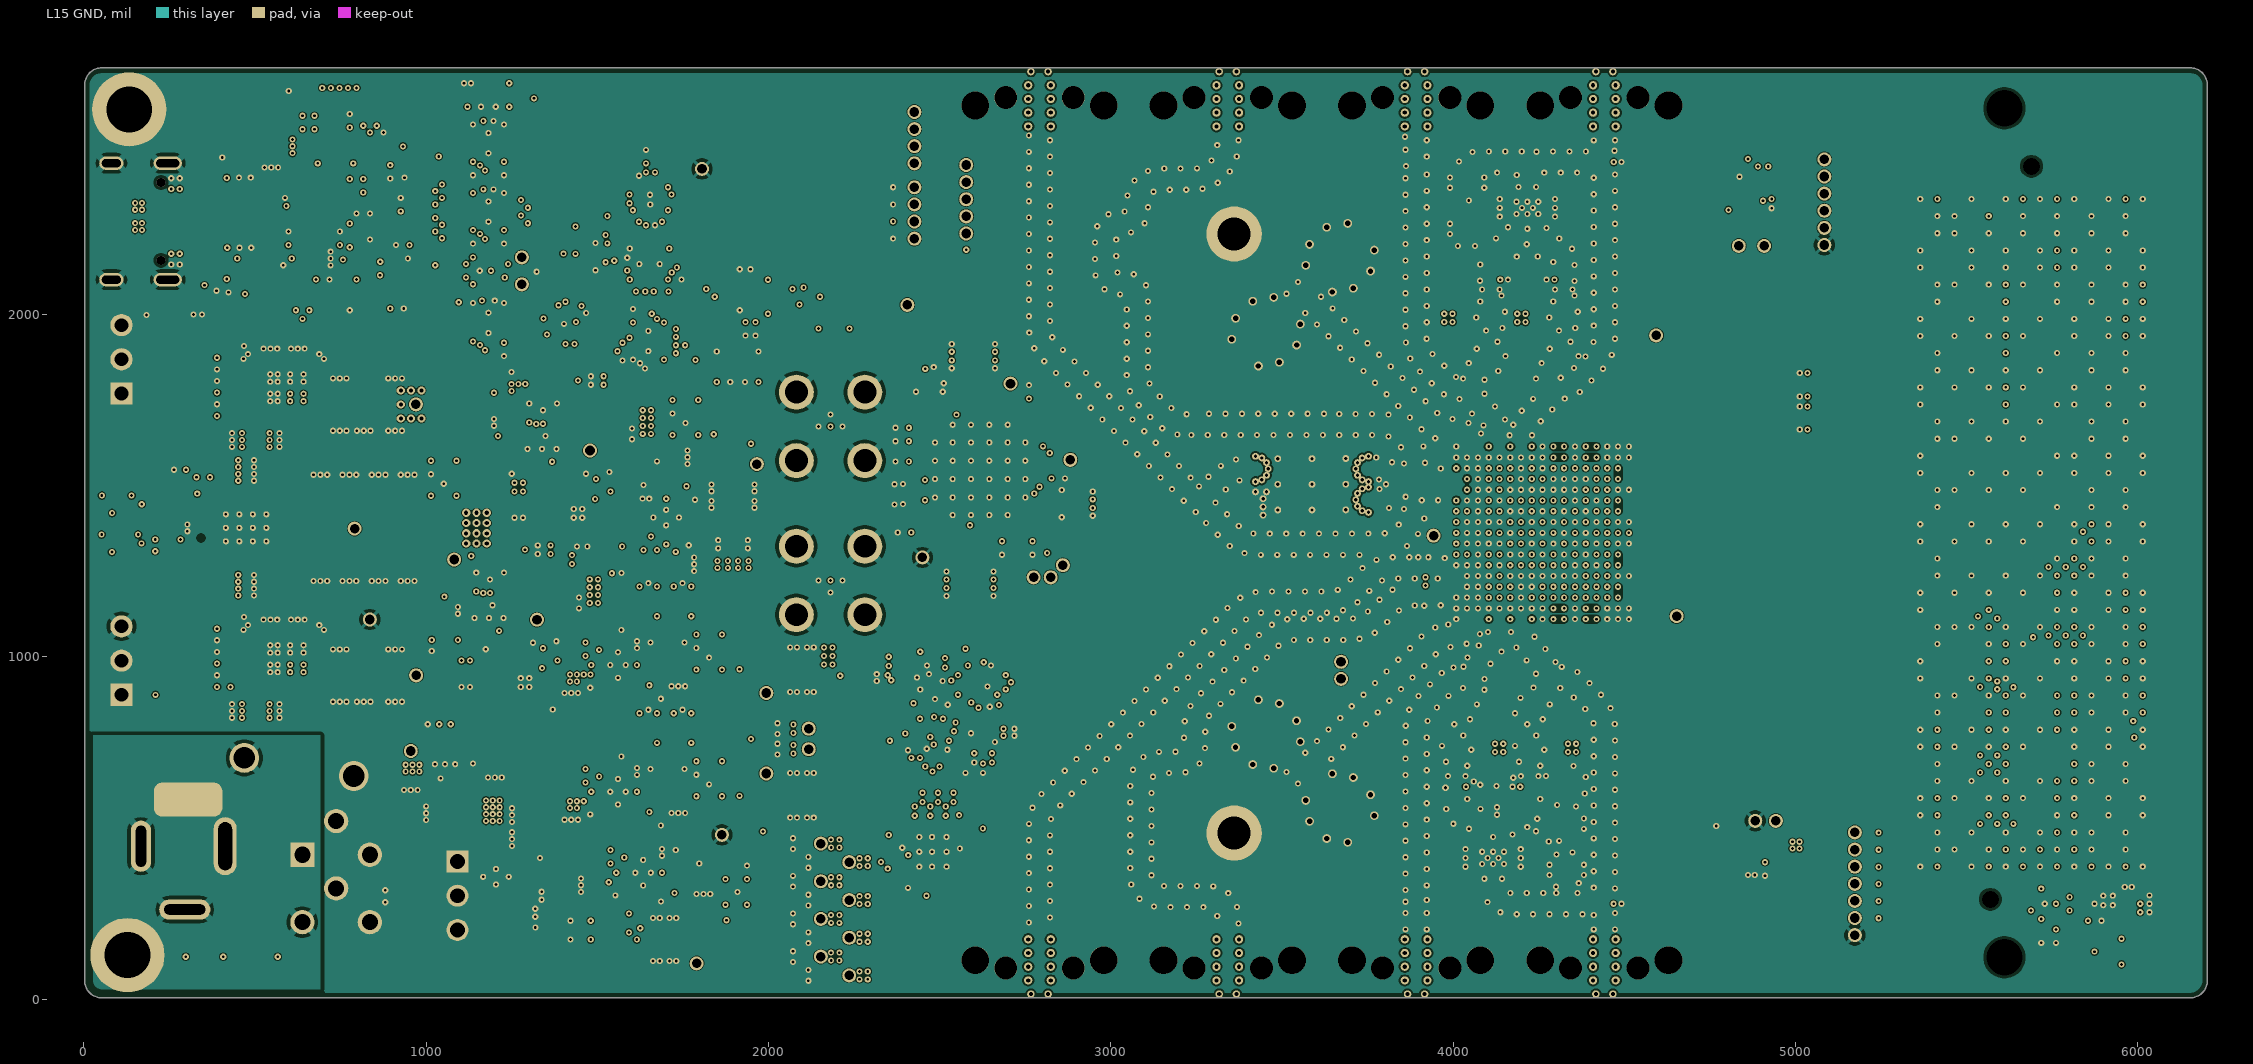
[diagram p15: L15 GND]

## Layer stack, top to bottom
Top Solder: solder mask 0.5, Solder Resist, Dk 3.5
Top Layer: signal copper 1.4
Dielectric 1: core 5.7, Megtron6, Dk 3.23
L2 GND: signal copper 1.4
Dielectric 2: prepreg 3.03, Megtron6, Dk 3.22
L3 PWR: signal copper 1.4
Dielectric 3: prepreg 3.03, Megtron6, Dk 3.22
L4 GND: signal copper 1.4
Dielectric 4: prepreg 3.03, Megtron6, Dk 3.22
L5 PWR: signal copper 1.4
Dielectric 5: prepreg 3.03, Megtron6, Dk 3.22
L6 GND: signal copper 1.4
Dielectric 6: prepreg 4.09, Megtron6, Dk 3.13
L7 SIG: signal copper 1.4
Dielectric 7: prepreg 3.86, Megtron6, Dk 3.34
L8 GND: signal copper 1.4
Dielectric 8: prepreg 3.03, Megtron6, Dk 3.22
L9 GND: signal copper 1.4
Dielectric 9: prepreg 3.86, Megtron6, Dk 3.34
L10 SIG: signal copper 1.4
Dielectric 10: prepreg 4.09, Megtron6, Dk 3.13
L11 GND: signal copper 1.4
Dielectric 11: prepreg 3.03, Megtron6, Dk 3.22
L12 PWR: signal copper 1.4
Dielectric 12: prepreg 3.03, Megtron6, Dk 3.22
L13 GND: signal copper 1.4
Dielectric 13: prepreg 3.03, Megtron6, Dk 3.22
L14 PWR: signal copper 1.4
Dielectric 14: prepreg 3.03, Megtron6, Dk 3.22
L15 GND: signal copper 1.4
Dielectric 15: core 5.7, Megtron6, Dk 3.23
Bottom Layer: signal copper 1.4
Board Layer Stack Bottom Solder: solder mask 0.5, Solder Resist, Dk 3.5

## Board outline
2.59,53.8 2.59,2670.34 cw(c52.59,2670.34) 52.59,2720.34 6152.59,2720.34 cw(c6152.59,2670.34) 6202.59,2670.34 6202.59,53.8 cw(c6152.59,53.8) 6152.59,3.8 52.59,3.8 cw(c52.59,53.8)

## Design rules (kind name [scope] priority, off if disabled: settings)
AcuteAngle [All] p1: minimum=4.50000000000000E+0001 checktracksonly=TRUE
AssemblyTestPointUsage [All] p1: valid=2
BackDrilling [All] p1: maxstublength=15 usetopbackdrill=TRUE usebottombackdrill=TRUE holeoversize=4 holetolplus=0 holetolminus=0
BoardOutlineClearance BoardOutlineClearance_1 [HasFootprint('HiRose-HK-LR-SR2-MicroStirp-6mil-Backdrill') or HasFootprint('HiRose-HK-LR-SR2-SWM1092-04A-MicroStirp-6mil-Female-Backdrill')] p1: gap=25 ignorepadtopadclearanceinfootprint=FALSE except(0: Arc-OutlineEdge Track-OutlineEdge SMDPad-OutlineEdge THPad-OutlineEdge Via-OutlineEdge Fill-OutlineEdge Poly-OutlineEdge Region-OutlineEdge Text-OutlineEdge)
BoardOutlineClearance BoardOutlineClearance_Poly_GND [OnCopper and IsPoly and InNet('GND')] p2: gap=15 ignorepadtopadclearanceinfootprint=FALSE // for poly ground to edge on layer 2 and less pullback on other layers
BoardOutlineClearance BoardOutlineClearance_Poly_PWR [OnCopper and IsPoly and not InNet('GND')] p3: gap=15 ignorepadtopadclearanceinfootprint=FALSE except(25: Poly-OutlineEdge) // for poly ground to edge on layer 2 and less pullback on other layers
BoardOutlineClearance BoardOutlineClearance_MountingHoles [OnCopper and InComponentClass('Mounting Holes')] p4: gap=39.37 ignorepadtopadclearanceinfootprint=FALSE
BoardOutlineClearance BoardOutlineClearance_Poly [OnCopper and IsPoly] p5: gap=25 ignorepadtopadclearanceinfootprint=FALSE // for non-ground polygons pull back
BoardOutlineClearance [OnCopper and Not InComponentClass('Logo') and not InComponentClass('FiducialMark') and not InRegion(1000,500,4000,800) and not InPoly and not HasFootprint('cbts130a')] p6: gap=25 ignorepadtopadclearanceinfootprint=FALSE
Clearance Clearance_Poly_GND [InPolygon and InNet('GND')] p1: gap=5 ignorepadtopadclearanceinfootprint=TRUE except(8: Arc-Hole Track-Hole SMDPad-Hole THPad-Hole Via-Hole Fill-Hole Poly-Hole Region-Hole Text-Hole; 12: Fill-Fill Fill-Poly Fill-Region Poly-Poly Poly-Region Region-Region)
Clearance Clearance_Outter_Layers [All vs (OnLayer('Top Layer') or OnLayer('Bottom Layer')) and not InAnyDifferentialPair] p2: gap=5 ignorepadtopadclearanceinfootprint=TRUE except(4: Arc-SMDPad Track-SMDPad; 8: Arc-Hole Track-Hole SMDPad-Hole THPad-Hole Via-Hole Fill-Hole Poly-Hole Region-Hole Text-Hole; 10: SMDPad-SMDPad THPad-Fill THPad-Poly THPad-Region; 12: Poly-Poly)
Clearance "Clearance_Outter_Layers 2" [All vs (OnLayer('Top Layer') or OnLayer('Bottom Layer')) and InAnyDifferentialPair] p3: gap=5 ignorepadtopadclearanceinfootprint=TRUE except(3: Arc-Arc Arc-Track Track-Track; 4: Arc-SMDPad; 8: Arc-Hole Track-Hole SMDPad-Hole THPad-Hole Via-Hole Fill-Hole Poly-Hole Region-Hole Text-Hole; 10: SMDPad-SMDPad THPad-Fill THPad-Poly THPad-Region; 12: Poly-Poly)
Clearance Clearance_Inner_Layers [All vs not OnLayer('Top Layer') and not OnLayer('Bottom Layer') and not InAnyDifferentialPair] p4: gap=5 ignorepadtopadclearanceinfootprint=TRUE except(8: Arc-Hole Track-Hole SMDPad-Hole THPad-Hole Via-Hole Fill-Hole Poly-Hole Region-Hole Text-Hole; 10: SMDPad-SMDPad THPad-Fill THPad-Poly THPad-Region; 12: Fill-Fill Fill-Poly Fill-Region Poly-Poly Poly-Region Region-Region; 15: Arc-Fill Arc-Poly Arc-Region Track-Fill Track-Poly Track-Region)
Clearance Clearance_Keepouts [((IsTrack Or IsArc) And Not InPoly) And IsFree and IsKeepOut vs ((IsTrack Or IsArc) And Not InPoly) And IsFree and IsKeepOut] p5: gap=0 ignorepadtopadclearanceinfootprint=FALSE
Clearance Clearance_Poly [InPolygon] p6: gap=5 ignorepadtopadclearanceinfootprint=TRUE except(8: Arc-Hole Track-Hole SMDPad-Hole THPad-Hole Via-Hole Fill-Hole Poly-Hole Region-Hole Text-Hole; 12: Fill-Fill Fill-Poly Fill-Region Poly-Poly Poly-Region Region-Region)
Clearance Clearance_FiducialMark [IsKeepOut and InComponentClass('FiducialMark') vs IsPad and InComponentClass('FiducialMark')] p7: gap=0 ignorepadtopadclearanceinfootprint=FALSE
ComponentClearance "ComponentClearance Part Overlap" [not HasFootprint('ProbePoint*') vs not HasFootprint('ProbePoint*')] p1: gap=0 collisioncheckmode=3 verticalgap=0 showdistances=FALSE
ComponentClearance ComponentClearance_MountingHoles_FiducialMarks [InComponentClass('Mounting Holes') vs InComponentClass('FiducialMark')] p2: gap=50 collisioncheckmode=3 verticalgap=10 showdistances=FALSE
ComponentClearance ComponentClearance_Shunt [InComponentClass('Header') vs InComponentClass('Shunt')] p3: gap=0 collisioncheckmode=3 verticalgap=0 showdistances=FALSE
ComponentClearance ComponentClearance_Logo [InComponentClass('Logo')] p4: gap=50 collisioncheckmode=3 verticalgap=10 showdistances=FALSE
ComponentClearance ComponentClearance_ScrewToNut [(HasFootprint('NY PMS 440 0025 PH')) vs (HasFootprint('Keystone_1902C'))] p5: gap=5 collisioncheckmode=3 verticalgap=10 showdistances=FALSE
ComponentClearance ComponentClearance_MountingHoles [InComponentClass('Mounting Holes')] p6: gap=100 collisioncheckmode=3 verticalgap=100000 showdistances=FALSE
ComponentClearance ComponentClearance_SmallPassives [HasFootprint('0201*') or HasFootprint('0402*') or HasFootprint('0508') or HasFootprint('0603*') or HasFootprint('0612') or HasFootprint('0805*') or HasFootprint('0815*') or HasFootprint('0830*') or HasFootprint('1206*') or HasFootprint('1210*') or HasFootprint('1808*') or HasFootprint('1812*') or HasFootprint('1825*') or HasFootprint('2010*') or HasFootprint('2220*') or HasFootprint('2225*') or HasFootprint('2512*') or HasFootprint('2728*') or HasFootprint('3518*') vs HasFootprint('0201*') or HasFootprint('0402*') or HasFootprint('0508') or HasFootprint('0603*') or HasFootprint('0612') or HasFootprint('0805*') or HasFootprint('0815*') or HasFootprint('0830*') or HasFootprint('1206*') or HasFootprint('1210*') or HasFootprint('1808*') or HasFootprint('1812*') or HasFootprint('1825*') or HasFootprint('2010*') or HasFootprint('2220*') or HasFootprint('2225*') or HasFootprint('2512*') or HasFootprint('2728*') or HasFootprint('3518*')] p7: gap=10 collisioncheckmode=3 verticalgap=10 showdistances=FALSE
ComponentClearance ComponentClearance_THtoSMT [IsThruComponent and not HasFootprint('ProbePoint_TH_40mil') vs IsSMTComponent] p8: gap=20 collisioncheckmode=3 verticalgap=0 showdistances=FALSE
ComponentClearance ComponentClearance_THtoTH [IsThruComponent and not HasFootprint('ProbePoint_TH_40mil') vs IsThruComponent and not HasFootprint('ProbePoint_TH_40mil')] p9: gap=30 collisioncheckmode=3 verticalgap=30 showdistances=FALSE
ComponentClearance [not HasFootprint('ProbePoint*') vs not HasFootprint('ProbePoint*')] p10: gap=10 collisioncheckmode=3 verticalgap=10 showdistances=FALSE
DiffPairsRouting [All] p1: maxlimit=15 minlimit=3 mostfreqgap=5 toplayer_prefgap=5.5 toplayer_minwidth=3 toplayer_maxwidth=15 toplayer_prefwidth=6.3 midlayer1_minwidth=3 midlayer1_maxwidth=15 midlayer1_prefwidth=3 midlayer2_minwidth=3 midlayer2_maxwidth=15 midlayer2_prefwidth=3 midlayer3_minwidth=3 midlayer3_maxwidth=15 midlayer3_prefwidth=3 midlayer4_minwidth=3 midlayer4_maxwidth=15 midlayer4_prefwidth=3 midlayer5_minwidth=3 midlayer5_maxwidth=15 midlayer5_prefwidth=3 midlayer6_minwidth=3 midlayer6_maxwidth=15 midlayer6_prefwidth=3 midlayer7_minwidth=3 midlayer7_maxwidth=15 midlayer7_prefwidth=3 midlayer8_minwidth=3 midlayer8_maxwidth=15 midlayer8_prefwidth=3 midlayer9_prefgap=6.5 midlayer9_minwidth=3 midlayer9_maxwidth=15 midlayer9_prefwidth=3.5 midlayer10_prefgap=6.5 midlayer10_minwidth=3 midlayer10_maxwidth=15 midlayer10_prefwidth=3.5 midlayer11_prefgap=4 midlayer11_minwidth=3 midlayer11_maxwidth=15 midlayer11_prefwidth=5 midlayer12_minwidth=3 midlayer12_maxwidth=15 midlayer12_prefwidth=4 midlayer13_prefgap=4 midlayer13_minwidth=3 midlayer13_maxwidth=15 midlayer13_prefwidth=5 midlayer14_prefgap=4 midlayer14_minwidth=3 midlayer14_maxwidth=15 midlayer14_prefwidth=5 bottomlayer_prefgap=5.5 bottomlayer_minwidth=3 bottomlayer_maxwidth=15 bottomlayer_prefwidth=6.3 maxuncoupledlength=1000
FabricationTestPointUsage TestPointUsage [All] p1: valid=2 allowmultiple=FALSE
FabricationTestpoint Testpoint [All] p1: side=3 testpointundercomponent=TRUE minsize=40 maxsize=100 preferedsize=60 minholesize=0 maxholesize=40 preferedholesize=32 testpointgrid=1 allowsidetop=TRUE allowsidebottom=TRUE usegrid=TRUE gridtolerance=0.01
FanoutControl Fanout_LCC [IsLCC] p1: bgadir=Out bgaviamode=Centered fanoutstyle=Auto fanoutdirection=Alternating viagrid=1 // Fanout_LCC (Default Rule)
FanoutControl Fanout_BGA [IsBGA] p2: bgadir=Out bgaviamode=Centered fanoutstyle=Auto fanoutdirection=Alternating viagrid=1 // Fanout_BGA (Default Rule)
FanoutControl Fanout_Default [All] p4: bgadir=Out bgaviamode=Centered fanoutstyle=Auto fanoutdirection=Alternating viagrid=1 // Fanout_Default (Default Rule)
FanoutControl Fanout_Small [(CompPinCount < 5)] p5: bgadir=Out bgaviamode=Centered fanoutstyle=Auto fanoutdirection=OutThenIn viagrid=1 // Fanout_Small (Default Rule)
HoleSize [All] p1: absolutevalues=TRUE maxlimit=2500 minlimit=5 maxpercent=80.000 minpercent=20.000
HoleToHoleClearance [All] p1: gap=8 allowstackedmicrovias=TRUE
MinimumSolderMaskSliver MinimumSolderMaskSliver_Logo [InComponentClass('Logo') vs InComponentClass('Logo')] p1: minsoldermaskwidth=0.7
MinimumSolderMaskSliver [All] p2: minsoldermaskwidth=3
PlaneConnect [All] p1: planeconnectstyle=Relief reliefexpansion=10 reliefentries=4 reliefconductorwidth=10 reliefairgap=10
PolygonConnect "PolygonConnect_Probe Point" [(InNet('GND') and HasFootprint('ProbePoint*'))] p1: thpad.connectstyle=Relief thpad.reliefconductorwidth=10 thpad.reliefentries=4 thpad.polygonreliefangle="45 Angle" thpad.airgapwidth=10 smdpad.connectstyle=Relief smdpad.reliefconductorwidth=10 smdpad.reliefentries=4 smdpad.polygonreliefangle="90 Angle" smdpad.airgapwidth=10 via.connectstyle=Relief via.reliefconductorwidth=10 via.reliefentries=4 via.polygonreliefangle="90 Angle" via.airgapwidth=10
PolygonConnect "PolygonConnect_RF Connector" [All vs (HasFootprint('RF Connector Dual Meg6') or HasFootprint('HiRose-HK-LR-SR2-SWM1092-04A-MicroStirp-6mil-Female-Backdrill') or HasFootprint('HiRose-HK-LR-SR2-SWM1092-04A-6-CPWG-Female-8mil-BackDrill') or HasFootprint('HiRose-HK-LR-SR2-MicroStirp-6mil-Backdrill') or HasFootprint('HiRose-HK-LR-SR2-CPWG-Block-8mil-BackDrill') or HasFootprint('HiRose-HK-LR-SR2-8mil-Blind') or HasFootprint('CINCH_145-0701-221')) AND InNet('GND')] p2: connectstyle=Direct reliefconductorwidth=10 reliefentries=4 polygonreliefangle="90 Angle" airgapwidth=10 // For direct connect on RF edge connector screw hole gnds
PolygonConnect PolygonConnect_Thermal_Pads [(HoleType = 'Round' && HoleSize < 39) and not (InNet('GND') and HasFootprint('ProbePoint*'))] p3: connectstyle=Direct reliefconductorwidth=25 reliefentries=4 polygonreliefangle="45 Angle" airgapwidth=5 // Designed to direct connect thermal pad vias
PolygonConnect [All] p4: thpad.connectstyle=Relief thpad.reliefconductorwidth=20 thpad.reliefentries=4 thpad.polygonreliefangle="45 Angle" thpad.airgapwidth=10 smdpad.connectstyle=Direct smdpad.reliefconductorwidth=10 smdpad.reliefentries=4 smdpad.polygonreliefangle="90 Angle" smdpad.airgapwidth=10 via.connectstyle=Direct via.reliefconductorwidth=10 via.reliefentries=4 via.polygonreliefangle="90 Angle" via.airgapwidth=10
RoutingTopology [All] p1: topology=Daisy_Balanced
RoutingVias ThermalPadVias [IsVia and InAnyComponent] p1: holewidth=8 width=18 viastyle="Through Hole" minholewidth=4 minwidth=10 maxholewidth=65 maxwidth=65
RoutingVias [All] p2: holewidth=8 width=18 viastyle="Through Hole" minholewidth=4 minwidth=10 maxholewidth=40 maxwidth=65
SMDEntry [All] p1: side=TRUE corner=TRUE anyangle=FALSE
SMDToCorner [All] p1: distance=0
SilkToBoardRegionClearance [Not ((IsComment or IsDesignator) And (Hide <> 'False')) and not InRegion(1000,500,4000,800)] p1:
SilkToSilkClearance [All] p1: silktosilkclearance=0
SilkToSolderMaskClearance SilkToComponentPadClearance [(IsPad or IsFill or IsRegion) and InAnycomponent] p1: minsilkscreentomaskgap=0 clearancetoexposedcopper=TRUE
SilkToSolderMaskClearance "Silk to Solder Mask Opening" [All] p2: minsilkscreentomaskgap=0 clearancetoexposedcopper=FALSE
SolderMaskExpansion [All] p1: expansion=1.97 istentingtop=FALSE
SupplyNets "Schematic Supply Nets_31" [InNet('Fan')] p1: voltage=0.000
SupplyNets "Schematic Supply Nets_25" [InNet('5V Fan')] p2: voltage=0.000
SupplyNets "Schematic Supply Nets_30" [InNet('3p3V_FTDI')] p3: voltage=0.000
SupplyNets "Schematic Supply Nets_29" [InNet('VDD_FPGA')] p4: voltage=0.000
SupplyNets "Schematic Supply Nets_28" [InNet('3p3V_Clock')] p5: voltage=0.000
SupplyNets "Schematic Supply Nets_27" [InNet('VDDLB')] p6: voltage=0.000
SupplyNets "Schematic Supply Nets_26" [InNet('VDDLA')] p7: voltage=0.000
SupplyNets "Schematic Supply Nets_24" [InNet('VDDL')] p8: voltage=0.000
SupplyNets "Schematic Supply Nets_23" [InNet('VDDCLK08')] p9: voltage=0.000
SupplyNets "Schematic Supply Nets_22" [InNet('VEEAM18')] p10: voltage=0.000
SupplyNets "Schematic Supply Nets_21" [InNet('VEEBM18')] p11: voltage=0.000
SupplyNets "Schematic Supply Nets_20" [InNet('VDDSYS18')] p12: voltage=0.000
SupplyNets "Schematic Supply Nets_19" [InNet('VDDCLK18')] p13: voltage=0.000
SupplyNets "Schematic Supply Nets_18" [InNet('VDDIO')] p14: voltage=0.000
SupplyNets "Schematic Supply Nets_17" [InNet('VDDA18A')] p15: voltage=0.000
SupplyNets "Schematic Supply Nets_16" [InNet('VDDCP18')] p16: voltage=0.000
SupplyNets "Schematic Supply Nets_15" [InNet('+1p8V')] p17: voltage=0.000
SupplyNets "Schematic Supply Nets_14" [InNet('VDDSP18')] p18: voltage=0.000
SupplyNets "Schematic Supply Nets_13" [InNet('VDDA18B')] p19: voltage=0.000
SupplyNets "Schematic Supply Nets_12" [InNet('VDDR18')] p20: voltage=0.000
SupplyNets "Schematic Supply Nets_11" [InNet('3p8V')] p21: voltage=0.000
SupplyNets "Schematic Supply Nets_10" [InNet('2p3V')] p22: voltage=0.000
SupplyNets "Schematic Supply Nets_9" [InNet('DVDD')] p23: voltage=0.000
SupplyNets "Schematic Supply Nets_8" [InNet('VADJ')] p24: voltage=0.000
SupplyNets "Schematic Supply Nets_7" [InNet('3p3V_EEPROM')] p25: voltage=0.000
SupplyNets "Schematic Supply Nets_6" [InNet('12V_FMC')] p26: voltage=0.000
SupplyNets "Schematic Supply Nets_5" [InNet('GND')] p27: voltage=0.000
SupplyNets "Schematic Supply Nets_4" [InNet('3p3V_FMC')] p28: voltage=0.000
SupplyNets "Schematic Supply Nets_3" [InNet('3p3V_Utility')] p29: voltage=0.000
SupplyNets "Schematic Supply Nets_2" [InNet('USB_5V')] p30: voltage=0.000
SupplyNets "Schematic Supply Nets_1" [InNet('3p3V_AUX')] p31: voltage=0.000
SupplyNets "Schematic Supply Nets" [InNet('12V')] p32: voltage=0.000
UnRoutedNet [All] p1: checkbadconnections=TRUE
Width [All] p1: maxlimit=100 minlimit=3 preferedwidth=11.5 toplayer_minwidth=4 toplayer_prefwidth=11 midlayer1_minwidth=4 midlayer1_prefwidth=6 midlayer2_minwidth=4 midlayer2_prefwidth=6 midlayer3_minwidth=4 midlayer3_prefwidth=6 midlayer4_minwidth=4 midlayer4_prefwidth=6 midlayer5_minwidth=4 midlayer5_prefwidth=6 midlayer6_minwidth=4 midlayer6_prefwidth=6 midlayer7_minwidth=4 midlayer7_prefwidth=6 midlayer8_minwidth=4 midlayer8_prefwidth=6 midlayer9_minwidth=4 midlayer10_minwidth=4 midlayer11_minwidth=4 midlayer12_minwidth=4 midlayer13_minwidth=4 midlayer14_minwidth=4 bottomlayer_prefwidth=11 minimp=50.000000 maximp=50.000000 favimp=50.000000
12 further rules are at their usual default settings.

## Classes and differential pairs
component class "LMK LVL Shift and Mux": C140 C141 C142 C143 C144 C145 C146 C147 PP32 PP33 PP34 PP35 PP36 PP37 PP38 PP39 PP41 PP42 PP43 PP44 PP45 R138 R139 R140 R141 R142 R143 R144 R145 R146 R147 R148 R149 R150 R151 R152 R153 R154 R155 R156 U47 U48 U49 U50 U51 U52 U53
component class "DUT Power": C236 C237 C238 C239 C240 C241 C242 C243 C244 C245 C246 C247 C248 C249 C250 C251 C252 C253 C254 C255 C256 C257 C258 C259 C260 C261 C262 C263 C264 C265 C266 C267 C268 C269 C270 C271 C272 C273 C274 C275 C276 C277 C278 C279 C280 C281 C282 C283 C284 C285 C286 C287 C288 C289 C290 C291 C292 C293 C294 C295 C296 C297 C298 C299 C300 C301 C302 C303 C304 C305 C306 C307 C308 C309 C310 C311 C312 C313 C314
net class Clocks&SYSREF: NetC182_2 NetC197_2 NetJ13_1 NetJ14_1
component class "DUT Outputs": C220 C221 C222 C223 C224 C225 C226 C227 C228 C229 C230 C231 C232 C233 C234 C235 J15 J16 J17 J18 R182 R183 R184 R185 R186 R187 R188 R189 R190 R191 R192 R193 T2 T3 T4 T5 T6 T7 T8 T9 U56 U57 U58 U59
net class SERDES: 0SRX_DUT_n 0SRX_DUT_p 0SRX_n 0SRX_p 1SRX_DUT_n 1SRX_DUT_p 1SRX_n 1SRX_p 2SRX_DUT_n 2SRX_DUT_p 2SRX_n 2SRX_p 3SRX_DUT_n 3SRX_DUT_p 3SRX_n 3SRX_p 4SRX_DUT_n 4SRX_DUT_p 4SRX_n 4SRX_p 5SRX_DUT_n 5SRX_DUT_p 5SRX_n 5SRX_p 6SRX_DUT_n 6SRX_DUT_p 6SRX_n 6SRX_p 7SRX_DUT_n 7SRX_DUT_p 7SRX_n 7SRX_p 8SRX_DUT_n 8SRX_DUT_p 8SRX_n 8SRX_p 9SRX_DUT_n 9SRX_DUT_p 9SRX_n 9SRX_p 10SRX_DUT_n 10SRX_DUT_p 10SRX_n 10SRX_p 11SRX_DUT_n 11SRX_DUT_p 11SRX_n 11SRX_p 12SRX_DUT_n 12SRX_DUT_p 12SRX_n 12SRX_p 13SRX_DUT_n 13SRX_DUT_p 13SRX_n 13SRX_p 14SRX_DUT_n 14SRX_DUT_p 14SRX_n 14SRX_p 15SRX_DUT_n 15SRX_DUT_p 15SRX_n 15SRX_p
component class "Power LMK": C104 C105 C106 C107 C108 C109 C110 C111 C112 FB6 FC1 PP29 R89 R90 R91 R92 R93 R94 R95 R96 U34 U35
net class PWR4: VDDCLK18 VDDIO VDDR18 VDDSP18 VDDSYS18
net class PWR3: VDDA18A VDDA18B VDDCP18 VEEAM18 VEEBM18
net class PWR2: VDDCLK08 VDDLA VDDLB
net class PWR1: DVDD
component class "Power Sense ADC": C11 C12 C13 C14 C15 C16 C17 C18 R12 R13 R14 R15 R16 R17 R18 R19 U5 U6 U7 U8
net class LMXK: 3p3V_Clock
net class LMK_Clocks: C8_N C8_P DAC_SYSREF_LMK_N DAC_SYSREF_LMK_P FPGA_CORECLK_n FPGA_CORECLK_p FPGA_SYSREF_n FPGA_SYSREF_p GBTCLK0_FMC_n GBTCLK0_FMC_p GBTCLK1_FMC_n GBTCLK1_FMC_p LMK_DCLKOUT4_N LMK_DCLKOUT4_P LMK_DCLKOUT6_N LMK_DCLKOUT6_P LMK_DCLKOUT10_N LMK_DCLKOUT10_P LMK_SDCLKOUT1_N LMK_SDCLKOUT1_P LMK_SDCLKOUT11_N LMK_SDCLKOUT11_P
component class "Clocking LMK04828": C148 C149 C150 C151 C152 C153 C154 C155 C156 C157 C158 C159 C160 C161 C162 C163 C164 C165 C166 C167 C168 C169 C170 C171 C172 C173 C174 C175 C176 C177 J4 J5 PP40 PP46 R157 R158 R159 R160 R161 R162 R163 R164 R165 R166 R167 R168 R169 R170 U54
component class "Power LDO 0p8V Analog": C80 C81 C82 C83 C84 C85 C86 C87 C88 C89 C90 C91 C92 C93 C94 C95 C96 C97 C98 C99 C100 C101 C102 C103 FB4 FB5 PP25 PP26 PP27 PP28 R67 R68 R69 R70 R71 R72 R73 R74 R75 R76 R77 R78 R79 R80 R81 R82 R83 R84 R85 R86 R87 R88 U26 U27 U28 U29 U30 U31 U32 U33
component class "Power LDO N1p8V Analog": C65 C66 C67 C68 C69 C70 C71 C72 C73 C74 C75 C76 C77 C78 C79 PP23 PP24 R51 R52 R53 R54 R55 R56 R57 R58 R59 R60 R61 R62 R63 R64 R65 R66 U17 U18 U19 U20 U21 U22 U23 U24 U25
component class "Power LDO 1p8V Analog": C48 C49 C50 C51 C52 C53 C54 C55 C56 C57 C58 C59 C60 C61 C62 C63 C64 FB3 PP14 PP15 PP16 PP17 PP18 PP19 PP20 PP21 PP22 R43 R44 R45 R46 R47 R48 R49 R50 U15 U16
component class "Power DC-DC Analog": C32 C33 C34 C35 C36 C37 C38 C39 C40 C41 C42 C43 C44 C45 C46 C47 FB1 FB2 PP12 PP13 R33 R34 R35 R36 R37 R38 R39 R40 R41 R42 U13 U14
component class "Power DC-DC Digital": C19 C20 C21 C22 C23 C24 C25 C26 C27 C28 C29 C30 C31 PP10 PP11 R20 R21 R22 R23 R24 R25 R26 R27 R28 R29 R30 R31 R32 U9 U10 U11 U12
component class "DUT IO": C178 C179 C180 C181 C182 C183 C184 C185 C186 C187 C188 C189 C190 C191 C192 C193 C194 C195 C196 C197 C198 C199 C200 C201 C202 C203 C204 C205 C206 C207 C208 C209 C210 C211 C212 C213 C214 C215 C216 C217 C218 C219 J7 J8 J9 J10 J11 J12 J13 J14 PP47 PP48 PP49 PP50 PP51 PP52 PP53 PP54 PP55 PP56 PP57 PP58 PP59 PP60 PP61 PP62 PP63 PP64 R171 R172 R173 R174 R175 R176 R177 R178 R179 R180 R181 R243 R244 R245 R246 R247 R248 T1 U1 U55
component class "I2C & DAC LVL Shift and MUX": C135 C136 C137 C138 C139 PP30 PP31 R118 R119 R120 R121 R122 R123 R124 R125 R126 R127 R128 R129 R130 R131 R132 R133 R134 R135 R136 R137 R250 R251 R252 R253 SW2 SW3 U43 U44 U45 U46
net class FMCPwr: 3p3V_FMC 12V_FMC VADJ
component class "FMC+ Sections F-H, J, K": R210 R211 R212 R213 R214 R215 R216 R217 R218 R219 R220 R221 R222 R223 R224 R225 R226 R227 R228
component class "USB Control FTDI": C113 C114 C115 C116 C117 C118 C119 C120 C121 C122 C123 C124 C125 C126 C127 C128 C129 C130 C131 C132 C133 C134 D4 FB7 FB8 J3 R97 R98 R99 R100 R101 R102 R103 R104 R105 R106 R107 R108 R109 R110 R111 R112 R113 R114 R115 R116 R117 U36 U37 U38 U39 U40 U41 U42 Y1
net class Power: 2p3V 3p3V_Clock 3p3V_FMC 3p3V_Utility 3p8V 12V 12V_FMC +1p8V DVDD NetC133_2 USB_5V VADJ VDD_FPGA VDDA18A VDDA18B VDDCLK08 VDDCLK18 VDDCP18 VDDIO VDDLA VDDLB VDDR18 VDDSP18 VDDSYS18 VEEAM18 VEEBM18
net class GenPwr: 2p3V 3p3V_Utility 3p8V 12V +1p8V NetC133_2 USB_5V VDD_FPGA
component class "12V Input, Efuse and 3p3V Utility": C1 C2 C3 C4 C5 C6 C7 C8 C9 C10 D1 D2 D3 F1 J2 PP1 PP2 PP3 PP4 PP5 PP6 PP7 PP8 PP9 Q1 R1 R2 R3 R4 R5 R6 R7 R8 R9 R10 R11 SW1 TP1 TP2 U2 U3 U4
component class "FMC+ Sections Y, Z, L, M": D6 D7 J1 Q2 Q3 R229 R230 R231 R232 R233 R234 R235 R236 R237 R238 R239 R240 R241 R242 R249
component class "FMC+ Sections A-E": C315 C316 D5 PP65 PP66 PP67 PP68 R194 R195 R196 R197 R198 R199 R200 R201 R202 R203 R204 R205 R206 R207 R208 R209 U60 U61
component class "Hardware & Mechanicals": !PCB? FID1 FID2 FID3 H1 H3 H5 H6 LBL1 LOGO1 Logo2 Logo3 Logo4 LOGO5 Logo6 Logo7 Logo8
differential pair DP21_C2M: +DP21_C2M_P -DP21_C2M_N
differential pair DP20_C2M: +DP20_C2M_P -DP20_C2M_N
differential pair DP15_C2M: +DP15_C2M_P -DP15_C2M_N
differential pair DP14_C2M: +DP14_C2M_P -DP14_C2M_N
differential pair C8: +C8_P -C8_N
differential pair TMSTPB: +TMSTPB_P -TMSTPB_N
differential pair TMSTPA: +TMSTPA_P -TMSTPA_N
differential pair 15SRX_DUT: +15SRX_DUT_p -15SRX_DUT_n
differential pair 14SRX_DUT: +14SRX_DUT_p -14SRX_DUT_n
differential pair 13SRX_DUT: +13SRX_DUT_p -13SRX_DUT_n
differential pair 12SRX_DUT: +12SRX_DUT_p -12SRX_DUT_n
differential pair 11SRX_DUT: +11SRX_DUT_p -11SRX_DUT_n
differential pair 10SRX_DUT: +10SRX_DUT_p -10SRX_DUT_n
differential pair 9SRX_DUT: +9SRX_DUT_p -9SRX_DUT_n
differential pair 8SRX_DUT: +8SRX_DUT_p -8SRX_DUT_n
differential pair 7SRX_DUT: +7SRX_DUT_p -7SRX_DUT_n
differential pair 6SRX_DUT: +6SRX_DUT_p -6SRX_DUT_n
differential pair 5SRX_DUT: +5SRX_DUT_p -5SRX_DUT_n
differential pair 4SRX_DUT: +4SRX_DUT_p -4SRX_DUT_n
differential pair 3SRX_DUT: +3SRX_DUT_p -3SRX_DUT_n
differential pair 2SRX_DUT: +2SRX_DUT_p -2SRX_DUT_n
differential pair 1SRX_DUT: +1SRX_DUT_p -1SRX_DUT_n
differential pair 0SRX_DUT: +0SRX_DUT_p -0SRX_DUT_n
differential pair 15SRX: +15SRX_p -15SRX_n
differential pair 14SRX: +14SRX_p -14SRX_n
differential pair 13SRX: +13SRX_p -13SRX_n
differential pair 12SRX: +12SRX_p -12SRX_n
differential pair 11SRX: +11SRX_p -11SRX_n
differential pair 10SRX: +10SRX_p -10SRX_n
differential pair 9SRX: +9SRX_p -9SRX_n
differential pair 8SRX: +8SRX_p -8SRX_n
differential pair 7SRX: +7SRX_p -7SRX_n
differential pair 6SRX: +6SRX_p -6SRX_n
differential pair 5SRX: +5SRX_p -5SRX_n
differential pair 4SRX: +4SRX_p -4SRX_n
differential pair 3SRX: +3SRX_p -3SRX_n
differential pair 2SRX: +2SRX_p -2SRX_n
differential pair 1SRX: +1SRX_p -1SRX_n
differential pair 0SRX: +0SRX_p -0SRX_n
differential pair LMK_SDCLKOUT11: +LMK_SDCLKOUT11_P -LMK_SDCLKOUT11_N
differential pair LMK_SDCLKOUT1: +LMK_SDCLKOUT1_P -LMK_SDCLKOUT1_N
differential pair LMK_DCLKOUT10: +LMK_DCLKOUT10_P -LMK_DCLKOUT10_N
differential pair LMK_DCLKOUT6: +LMK_DCLKOUT6_P -LMK_DCLKOUT6_N
differential pair LMK_DCLKOUT4: +LMK_DCLKOUT4_P -LMK_DCLKOUT4_N
differential pair GBTCLK1_FMC: +GBTCLK1_FMC_p -GBTCLK1_FMC_n
differential pair GBTCLK0_FMC: +GBTCLK0_FMC_p -GBTCLK0_FMC_n
differential pair FPGA_SYSREF: +FPGA_SYSREF_p -FPGA_SYSREF_n
differential pair FPGA_CORECLK: +FPGA_CORECLK_p -FPGA_CORECLK_n
differential pair DAC_SYSREF_LMK: +DAC_SYSREF_LMK_P -DAC_SYSREF_LMK_N

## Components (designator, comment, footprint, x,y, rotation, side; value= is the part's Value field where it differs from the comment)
C1 "C2012X7R1H105K125AB" 0805L_cap 835.49,520.23 r90 bottom value="1 uF"
C2 "C2012X7R1H105K125AB" 0805L_cap 1236.15,537.44 r180 bottom value="1 uF"
C3 "C2012X7R1H105K125AB" 0805L_cap 1236.15,467.44 r180 bottom value="1 uF"
C4 "CGA3E2X7R1H102K080AA" 0603L_cap 1306.69,252.2 r180 bottom value="0.001 uF"
C5 "CGA3E2X7R1H102K080AA" 0603L_cap 1325.46,302.2 r180 bottom value="0.001 uF"
C6 "08053D106KAT4A" 0805L_cap 1200.72,632.69 r270 bottom value="10 uF"
C7 "C1005X5R1A475K050BC" 0402L_cap#1 4910.77,380.2 r90 bottom value="4.7 uF"
C8 "C1005X5R1A475K050BC" 0402L_cap#1 4768.4,486.07 r270 bottom value="4.7 uF"
C9 "C2012X7S1A226M125AC" 0805L_cap 955.09,625.27 r90 bottom value="22 uF"
C10 "CGA2B2X7R1H332K050BA" 0402L_cap#1 1136.48,707.94 r90 bottom value="3300 pF"
C11 "C0603X5R1C104K030BC" 0201_cap 2523.63,875.86 r270 bottom value="0.1 uF"
C12 "C0603X5R1C104K030BC" 0201_cap 2486.04,860.32 r90 bottom value="0.1 uF"
C13 "C0603X5R1C104K030BC" 0201_cap 2332.37,949.26 r180 bottom value="0.1 uF"
C14 "C0603X5R1C104K030BC" 0201_cap 2332.37,929.57 r180 bottom value="0.1 uF"
C15 "C0603X5R1C104K030BC" 0201_cap 2657.14,859.24 r180 bottom value="0.1 uF"
C16 "C0603X5R1C104K030BC" 0201_cap 2702.1,789.97 r0 bottom value="0.1 uF"
C17 "C0603X5R1C104K030BC" 0201_cap 2702.1,769.22 r0 bottom value="0.1 uF"
C18 "C0603X5R1C104K030BC" 0201_cap 2412.29,715.79 r90 bottom value="0.1 uF"
C19 "GRT155R71E104KE01J" 0402L_cap#1 1014.02,1552.93 r90 bottom value="0.1 uF"
C20 "C3216X5R1E476M160AC" 1206L_cap 474.09,1204.07 r180 bottom value="47 uF"
C21 "C3216X5R1E476M160AC" 1206L_cap 474.09,1549.11 r180 bottom value="47 uF"
C22 "GMC31X5R107M10NT" 1206L_cap 690.91,1244.43 r90 bottom value="100 uF"
C23 "GMC31X5R107M10NT" 1206L_cap 775.91,1244.43 r90 bottom value="100 uF"
C24 "GMC31X5R107M10NT" 1206L_cap 860.91,1244.43 r90 bottom value="100 uF"
C25 "GMC31X5R107M10NT" 1206L_cap 945.91,1244.43 r90 bottom value="100 uF"
C26 "0402YD103KAT2A" 0402L_cap#1 262.83,1308.34 r0 bottom value="0.01 uF"
C27 "GMC31X5R107M10NT" 1206L_cap 690.91,1508.76 r270 bottom value="100 uF"
C28 "GMC31X5R107M10NT" 1206L_cap 775.91,1508.76 r270 bottom value="100 uF"
C29 "GMC31X5R107M10NT" 1206L_cap 860.91,1508.76 r270 bottom value="100 uF"
C30 "GMC31X5R107M10NT" 1206L_cap 945.91,1508.76 r270 bottom value="100 uF"
C31 "CM05X5R225K10AH" 0402L_cap#1 262.83,1420.71 r0 bottom value="2.2 uF"
C32 "C2012X7S1E106K125AC" 0805L_cap 447.29,841.74 r0 bottom value="10 uF"
C33 "C2012X7S1E106K125AC" 0805L_cap 557.35,841.74 r180 bottom value="10 uF"
C34 "C2012X7S1A226M125AC" 0805L_cap 747.63,1007.21 r270 bottom value="22 uF"
C35 "C2012X7S1A226M125AC" 0805L_cap 817.63,883.2 r90 bottom value="22 uF"
C36 "C2012X7S1A226M125AC" 0805L_cap 747.63,883.2 r90 bottom value="22 uF"
C37 "C2012X7S1A226M125AC" 0805L_cap 909.36,1007.21 r270 bottom value="22 uF"
C38 "C2012X7S1A226M125AC" 0805L_cap 909.36,883.2 r90 bottom value="22 uF"
C39 "CGA2B1X5R1C224M050BC" 0402L_cap#1 409.06,946.11 r180 bottom value="0.22 uF"
C40 "C2012X7S1E106K125AC" 0805L_cap 447.3,1633.27 r0 bottom value="10 uF"
C41 "C2012X7S1E106K125AC" 0805L_cap 557.35,1633.27 r180 bottom value="10 uF"
C42 "C2012X7S1A226M125AC" 0805L_cap 747.63,1798.74 r270 bottom value="22 uF"
C43 "C2012X7S1A226M125AC" 0805L_cap 817.63,1674.73 r90 bottom value="22 uF"
C44 "C2012X7S1A226M125AC" 0805L_cap 747.63,1674.73 r90 bottom value="22 uF"
C45 "C2012X7S1A226M125AC" 0805L_cap 909.36,1798.74 r270 bottom value="22 uF"
C46 "C2012X7S1A226M125AC" 0805L_cap 909.36,1674.73 r90 bottom value="22 uF"
C47 "CGA2B1X5R1C224M050BC" 0402L_cap#1 409.06,1737.64 r180 bottom value="0.22 uF"
C48 "GRT155R71E104KE01J" 0402L_cap#1 1937,370.29 r270 bottom value="0.1 uF"
C49 "C2012X7S1E106K125AC" 0805L_cap 1467.63,332.69 r0 bottom value="10 uF"
C50 "GRT155R71E104KE01J" 0402L_cap#1 1552.58,322.85 r90 bottom value="0.1 uF"
C51 "NFM18PC105R0J3D" NFM18PC 2071.36,454.37 r0 bottom value="1 µF"
C52 "C2012X7S1E106K125AC" 0805L_cap 1809.89,322.85 r90 bottom value="10 uF"
C53 "GRM188R60J476ME15D" 0603L_cap 1720.58,126.55 r90 bottom value="47 uF"
C54 "GRM188R60J476ME15D" 0603L_cap 1672.37,221.99 r270 bottom value="47 uF"
C55 "GRM188R60J476ME15D" 0603L_cap 1720.58,221.67 r270 bottom value="47 uF"
C56 "GRM188R60J476ME15D" 0603L_cap 1672.37,126.87 r90 bottom value="47 uF"
C57 "NFM18PC105R0J3D" NFM18PC 2071.36,124.37 r0 bottom value="1 µF"
C58 "C1005X5R1E105K050BC" 0402L_cap#2 1728.89,415.77 r270 bottom value="1 uF"
C59 "NFM18PC105R0J3D" NFM18PC 2116.36,69.37 r0 bottom value="1 µF"
C60 "NFM18PC105R0J3D" NFM18PC 2071.36,234.37 r0 bottom value="1 µF"
C61 "NFM18PC105R0J3D" NFM18PC 2116.36,289.37 r0 bottom value="1 µF"
C62 "NFM18PC105R0J3D" NFM18PC 2071.36,344.37 r0 bottom value="1 µF"
C63 "NFM18PC105R0J3D" NFM18PC 2116.36,399.37 r0 bottom value="1 µF"
C64 "NFM18PC105R0J3D" NFM18PC 2116.36,179.37 r0 bottom value="1 µF"
C65 "GRM033Z71C104KE14J" 0201_cap 1016.14,1033.13 r90 bottom value="0.1 uF"
C66 "0603ZD106KAT2A" 0603L_cap 1146.3,1218.17 r270 bottom value="10 uF"
C67 "C1005X5R1A225K050BC" 0402L_cap#1 1186.77,1206.36 r270 bottom value="2.2 uF"
C68 "GRM033R61A105ME44D" 0201_cap 1183.7,1049.81 r0 bottom value="1 uF"
C69 "NFM18PC105R0J3D" NFM18PC 1446.12,1157.22 r0 bottom value="1 µF"
C70 "0603ZD106KAT2A" 0603L_cap 1380.28,1073.06 r90 bottom value="10 uF"
C71 "0603ZD106KAT2A" 0603L_cap 1227.3,1218.17 r270 bottom value="10 uF"
C72 "GRM033Z71C104KE14J" 0201_cap 1553.46,1244.12 r180 bottom value="0.1 uF"
C73 "GRM033Z71C104KE14J" 0201_cap 1249.3,1814.46 r270 bottom value="0.1 uF"
C74 "0603ZD106KAT2A" 0603L_cap 1301.11,1712.19 r270 bottom value="10 uF"
C75 "C1005X5R1A225K050BC" 0402L_cap#1 1341.59,1700.38 r270 bottom value="2.2 uF"
C76 "GRM033R61A105ME44D" 0201_cap 1338.51,1539.83 r0 bottom value="1 uF"
C77 "NFM18PC105R0J3D" NFM18PC 1600.94,1651.23 r0 bottom value="1 µF"
C78 "0603ZD106KAT2A" 0603L_cap 1535.1,1567.07 r90 bottom value="10 uF"
C79 "0603ZD106KAT2A" 0603L_cap 1382.11,1712.19 r270 bottom value="10 uF"
C80 "GRT155R71E104KE01J" 0402L_cap#1 1791.17,675.15 r90 bottom value="0.1 uF"
C81 "C2012X7S1E106K125AC" 0805L_cap 1423.79,539.71 r90 bottom value="10 uF"
C82 "GRT155R71E104KE01J" 0402L_cap#1 1479.21,559.4 r90 bottom value="0.1 uF"
C83 "NFM18PC105R0J3D" NFM18PC 2026.02,730.04 r0 bottom value="1 µF"
C84 "C2012X7S1A226M125AC" 0805L_cap 1736.52,559.4 r90 bottom value="22 uF"
C85 "GRM188R60J476ME15D" 0603L_cap 2073.1,547.67 r90 bottom value="47 uF"
C86 "GRM188R60J476ME15D" 0603L_cap 2122.1,642.78 r270 bottom value="47 uF"
C87 "GRM188R60J476ME15D" 0603L_cap 2122.1,547.67 r90 bottom value="47 uF"
C88 "GRM188R60J476ME15D" 0603L_cap 2073.1,642.78 r270 bottom value="47 uF"
C89 "NFM18PC105R0J3D" NFM18PC 2026.02,790.04 r0 bottom value="1 µF"
C90 "C1005X5R1A475K050BE" 0402L_cap#1 1655.52,652.31 r270 bottom value="4.7 uF"
C91 "GRT155R71E104KE01J" 0402L_cap#1 1791.17,1045.15 r90 bottom value="0.1 uF"
C92 "C2012X7S1E106K125AC" 0805L_cap 1423.79,909.71 r90 bottom value="10 uF"
C93 "GRT155R71E104KE01J" 0402L_cap#1 1479.21,929.4 r90 bottom value="0.1 uF"
C94 "C2012X7S1A226M125AC" 0805L_cap 1736.52,929.4 r90 bottom value="22 uF"
C95 "GRM188R60J476ME15D" 0603L_cap 2073.1,914.91 r90 bottom value="47 uF"
C96 "GRM188R60J476ME15D" 0603L_cap 2122.1,1010.03 r270 bottom value="47 uF"
C97 "GRM188R60J476ME15D" 0603L_cap 2122.1,914.91 r90 bottom value="47 uF"
C98 "GRM188R60J476ME15D" 0603L_cap 2073.1,1010.03 r270 bottom value="47 uF"
C99 "C1005X5R1A475K050BE" 0402L_cap#1 1655.52,1022.31 r270 bottom value="4.7 uF"
C100 "C0603X5R1C104K030BC" 0201_cap 1734.39,835.18 r0 top value="0.1 uF"
C101 "C0603X5R1C104K030BC" 0201_cap 1634.39,835.18 r0 top value="0.1 uF"
C102 "C0603X5R1C104K030BC" 0201_cap 1634.39,1205.18 r0 top value="0.1 uF"
C103 "C0603X5R1C104K030BC" 0201_cap 1734.39,1205.18 r0 top value="0.1 uF"
C104 "GRT155R71E104KE01J" 0402L_cap#1 1719.79,1730.33 r90 bottom value="0.1 uF"
C105 "C2012X7S1E106K125AC" 0805L_cap 1767.23,1270.17 r180 bottom value="10 uF"
C106 "GRT155R71E104KE01J" 0402L_cap#1 1747.54,1325.6 r180 bottom value="0.1 uF"
C107 "C2012X7S1E106K125AC" 0805L_cap 1747.54,1582.9 r180 bottom value="10 uF"
C108 "GRM188R60J476ME15D" 0603L_cap 1943.84,1493.6 r180 bottom value="47 uF"
C109 "GRM188R60J476ME15D" 0603L_cap 1848.41,1445.38 r0 bottom value="47 uF"
C110 "GRM188R60J476ME15D" 0603L_cap 1848.72,1493.6 r0 bottom value="47 uF"
C111 "GRM188R60J476ME15D" 0603L_cap 1943.53,1445.38 r180 bottom value="47 uF"
C112 "C1005X5R1E105K050BC" 0402L_cap#2 1654.63,1501.9 r0 bottom value="1 uF"
C113 "GRT155R71E104KE01J" 0402L_cap#1 747.88,2222.4 r270 bottom value="0.1 uF"
C114 "C1005X5R1A475K050BC" 0402L_cap#1 454.97,2214.36 r90 top value="4.7 uF"
C115 "04023D104KAT2A" 0402L_cap#1 488.97,2214.36 r90 top value="0.1 uF"
C116 "C1005X5R1A475K050BC" 0402L_cap#1 453.59,2379.88 r270 top value="4.7 uF"
C117 "04023D104KAT2A" 0402L_cap#1 487.59,2379.88 r270 top value="0.1 uF"
C118 "CGA3E1X5R1A335K080AC" 0603L_cap 924.01,2202.71 r0 bottom value="3.3 uF"
C119 "GRT155R71E104KE01J" 0402L_cap#1 1136.57,2226.45 r90 top value="0.1 uF"
C120 "GRT155R71E104KE01J" 0402L_cap#1 1227.12,2226.45 r90 top value="0.1 uF"
C121 "GRT155R71E104KE01J" 0402L_cap#1 1136.57,2426.45 r90 top value="0.1 uF"
C122 "GRT155R71E104KE01J" 0402L_cap#1 1227.12,2426.45 r90 top value="0.1 uF"
C123 "04023D104KAT2A" 0402L_cap#1 925.57,2320.82 r270 bottom value="0.1 uF"
C124 "04023D104KAT2A" 0402L_cap#1 587.52,2163.34 r0 bottom value="0.1 uF"
C125 "04023D104KAT2A" 0402L_cap#1 698.19,2102.12 r180 bottom value="0.1 uF"
C126 "04023D104KAT2A" 0402L_cap#1 776.93,2565.78 r270 bottom value="0.1 uF"
C127 "04023D104KAT2A" 0402L_cap#1 914.72,2017.12 r180 bottom value="0.1 uF"
C128 "04023D104KAT2A" 0402L_cap#1 895.04,2416.41 r90 bottom value="0.1 uF"
C129 "GJM0336C1E180JB01J" 0201_cap 391.5,2471.16 r135 top value="18 pF"
C130 "GJM0336C1E180JB01J" 0201_cap 585.64,2665.3 r135 top value="18 pF"
C131 "GRT155R71E104KE01J" 0402L_cap#1 1140.51,2606.41 r180 top value="0.1 uF"
C132 "C1005X5R1A475K050BC" 0402L_cap#1 367.64,2069.42 r180 bottom value="4.7 uF"
C133 "CM05X5R105K25AH" 0402L_cap#1 183.07,2017.83 r90 bottom value="1 uF"
C134 "GRT155R71E104KE01J" 0402L_cap#1 1223.19,2606.41 r0 top value="0.1 uF"
C135 "GRT155R71E104KE01J" 0402L_cap#1 1169.76,2127.4 r0 top value="0.1 uF"
C136 "GRT155R71E104KE01J" 0402L_cap#1 1868.66,1802.71 r0 bottom value="0.1 uF"
C137 "GRT155R71E104KE01J" 0402L_cap#1 1951.34,1802.71 r180 bottom value="0.1 uF"
C138 "GRT155R71E104KE01J" 0402L_cap#1 1932.53,1957.77 r270 bottom value="0.1 uF"
C139 "GRT155R71E104KE01J" 0402L_cap#1 1962.28,1957.77 r270 bottom value="0.1 uF"
C140 "GRT155R71E104KE01J" 0402L_cap#1 1642.36,2460.98 r270 top value="0.1 uF"
C141 "GRT155R71E104KE01J" 0402L_cap#1 1726.25,2101.83 r0 top value="0.1 uF"
C142 "GRT155R71E104KE01J" 0402L_cap#1 1696.31,2178.46 r225 top value="0.1 uF"
C143 "GRT155R71E104KE01J" 0402L_cap#1 1660.03,1973.24 r225 top value="0.1 uF"
C144 "GRT155R71E104KE01J" 0402L_cap#1 1603.83,1996.1 r90 top value="0.1 uF"
C145 "GRT155R71E104KE01J" 0402L_cap#1 1469.47,1984.38 r225 top value="0.1 uF"
C146 "GRT155R71E104KE01J" 0402L_cap#1 1170.92,1924.31 r225 top value="0.1 uF"
C147 "GRT155R71E104KE01J" 0402L_cap#1 1227.12,1897.79 r270 top value="0.1 uF"
C148 "GRT155R71E104KE01J" 0402L_cap#1 2397.27,1363.19 r180 bottom value="0.1 uF"
C149 "GRT155R71E104KE01J" 0402L_cap#1 2846.1,1521.22 r0 bottom value="0.1 uF"
C150 "GRT155R71E104KE01J" 0402L_cap#1 2390.27,1629.49 r180 bottom value="0.1 uF"
C151 "GRT155R71E104KE01J" 0402L_cap#1 2770.74,1317.92 r270 bottom value="0.1 uF"
C152 "GRT155R71E104KE01J" 0402L_cap#1 2588.66,1404.1 r90 top value="0.1 uF"
C153 "GRT155R71E104KE01J" 0402L_cap#1 2390.27,1668.86 r180 bottom value="0.1 uF"
C154 "GRT155R71E104KE01J" 0402L_cap#1 2476.45,1457.25 r0 top value="0.1 uF"
C155 "GRT155R71E104KE01J" 0402L_cap#1 2476.45,1516.3 r0 top value="0.1 uF"
C156 "GRT155R71E104KE01J" 0402L_cap#1 2390.27,1570.44 r180 bottom value="0.1 uF"
C157 "GRT155R71E104KE01J" 0402L_cap#1 2549.29,1687.56 r270 top value="0.1 uF"
C158 "GRT155R71E104KE01J" 0402L_cap#1 2682.16,1317.92 r270 bottom value="0.1 uF"
C159 "GRT155R71E104KE01J" 0402L_cap#1 2760.9,1773.74 r90 bottom value="0.1 uF"
C160 "GRM033Z71C104KE14D" 0201_cap 2403.93,1476.93 r0 bottom value="0.1 uF"
C161 "GRM033Z71C104KE14D" 0201_cap 2403.93,1499.98 r0 bottom value="0.1 uF"
C162 "GRM033Z71C104KE14D" 0201_cap 2892.44,1459.93 r180 bottom value="0.1 uF"
C163 "GRM033Z71C104KE14D" 0201_cap 2892.44,1434.88 r180 bottom value="0.1 uF"
C164 "GRM033Z71C104KE14D" 0201_cap 2403.93,1440.92 r0 bottom value="0.1 uF"
C165 "GRM033Z71C104KE14D" 0201_cap 2403.93,1417.88 r0 bottom value="0.1 uF"
C166 "GRM033Z71C104KE14D" 0201_cap 2630.71,1296.58 r90 bottom value="0.1 uF"
C167 "GRM033Z71C104KE14D" 0201_cap 2605.66,1296.58 r90 bottom value="0.1 uF"
C168 "GRM033Z71C104KE14D" 0201_cap 2571.65,1296.58 r90 bottom value="0.1 uF"
C169 "GRM033Z71C104KE14D" 0201_cap 2546.61,1296.58 r90 bottom value="0.1 uF"
C170 "GRM033Z71C104KE14D" 0201_cap 2457.67,1810.08 r270 bottom value="0.1 uF"
C171 "GRM033Z71C104KE14D" 0201_cap 2481.85,1810.08 r270 bottom value="0.1 uF"
C172 "GRM033Z71C104KE14D" 0201_cap 2561.29,1795.08 r270 bottom value="0.1 uF"
C173 "GRM033Z71C104KE14D" 0201_cap 2586.73,1795.08 r270 bottom value="0.1 uF"
C174 "GRM033Z71C104KE14D" 0201_cap 2610.27,1795.08 r270 bottom value="0.1 uF"
C175 "GRM033Z71C104KE14D" 0201_cap 2635.71,1795.08 r270 bottom value="0.1 uF"
C176 "C1608X5R1A106K080AC" 0603L_cap 2764.14,1514.36 r0 top value="10 uF"
C177 "GRT155R71E104KE01J" 0402L_cap#1 2757.69,1467.83 r180 top value="0.1 uF"
C178 "0201BB104KW160" 0201_cap 4623.99,965.52 r0 bottom value="0.1 uF"
C179 "0201BB104KW160" 0201_cap 4623.99,942.52 r0 bottom value="0.1 uF"
C180 "0201BB104KW160" 0201_cap 4623.99,918.17 r0 bottom value="0.1 uF"
C181 "0201BB104KW160" 0201_cap 4623.99,895.17 r0 bottom value="0.1 uF"
C182 "0201BB104KW160" 0201_cap 3265.52,1446.85 r135 top value="0.1 uF"
C183 "0201BB104KW160" 0201_cap 3886.85,1476.93 r90 top value="0.1 uF"
C184 "0201BB104KW160" 0201_cap 3265.52,1462.44 r225 top value="0.1 uF"
C185 "0201BB104KW160" 0201_cap 4623.99,1012.76 r0 bottom value="0.1 uF"
C186 "0201BB104KW160" 0201_cap 3875.83,1487.95 r180 top value="0.1 uF"
C187 "0201BB104KW160" 0201_cap 4623.99,989.76 r0 bottom value="0.1 uF"
C188 "0201BB104KW160" 0201_cap 4623.99,1060 r0 bottom value="0.1 uF"
C189 "0201BB104KW160" 0201_cap 4623.99,1037 r0 bottom value="0.1 uF"
C190 "0201BB104KW160" 0201_cap 3875.83,1519.45 r180 top value="0.1 uF"
C191 "0201BB104KW160" 0201_cap 4600.19,1200.19 r0 top value="0.1 uF"
C192 "0201BB104KW160" 0201_cap 3886.85,1530.47 r270 top value="0.1 uF"
C193 "0201BB104KW160" 0201_cap 4600.19,1177.19 r0 top value="0.1 uF"
C194 "0201BB104KW160" 0201_cap 4568.69,1200.24 r0 bottom value="0.1 uF"
C195 "0201BB104KW160" 0201_cap 4568.69,1177.24 r0 bottom value="0.1 uF"
C196 "0201BB104KW160" 0201_cap 4600.19,1294.68 r0 top value="0.1 uF"
C197 "0201BB104KW160" 0201_cap 3221.01,1678.7 r180 top value="0.1 uF"
C198 "0201BB104KW160" 0201_cap 4600.19,1271.68 r0 top value="0.1 uF"
C199 "0201BB104KW160" 0201_cap 4568.69,1294.73 r0 bottom value="0.1 uF"
C200 "0201BB104KW160" 0201_cap 4568.69,1271.73 r0 bottom value="0.1 uF"
C201 "0201BB104KW160" 0201_cap 4623.99,1781.42 r0 bottom value="0.1 uF"
C202 "0201BB104KW160" 0201_cap 4623.99,1758.42 r0 bottom value="0.1 uF"
C203 "0201BB104KW160" 0201_cap 4623.99,1828.76 r0 bottom value="0.1 uF"
C204 "0201BB104KW160" 0201_cap 4623.99,1805.76 r0 bottom value="0.1 uF"
C205 "0201BB104KW160" 0201_cap 4623.99,1734.18 r0 bottom value="0.1 uF"
C206 "0201BB104KW160" 0201_cap 4623.99,1711.18 r0 bottom value="0.1 uF"
C207 "0201BB104KW160" 0201_cap 4623.99,1686.94 r0 bottom value="0.1 uF"
C208 "0201BB104KW160" 0201_cap 4623.99,1663.94 r0 bottom value="0.1 uF"
C209 "0201BB104KW160" 0201_cap 4600.19,1546.65 r0 top value="0.1 uF"
C210 "0201BB104KW160" 0201_cap 4600.19,1523.65 r0 top value="0.1 uF"
C211 "0201BB104KW160" 0201_cap 4568.69,1546.7 r0 bottom value="0.1 uF"
C212 "0201BB104KW160" 0201_cap 4568.69,1523.7 r0 bottom value="0.1 uF"
C213 "0201BB104KW160" 0201_cap 4600.19,1452.16 r0 top value="0.1 uF"
C214 "0201BB104KW160" 0201_cap 4600.19,1429.16 r0 top value="0.1 uF"
C215 "0201BB104KW160" 0201_cap 4568.69,1452.21 r0 bottom value="0.1 uF"
C216 "0201BB104KW160" 0201_cap 4568.69,1429.21 r0 bottom value="0.1 uF"
C217 "GRM033Z71C104KE14D" 0201_cap 4930.11,2326.08 r90 bottom value="0.1 uF"
C218 "GRM033R71C101JA01D" 0201_cap 4870.58,2305.14 r0 bottom value="100 pF"
C219 "GRM033Z71C104KE14D" 0201L#1 4020.05,1388.46 r180 bottom value=0.1uF
C220 "0201BB104KW160" 0201_cap 4223.02,609.61 r90 top value="0.1 uF"
C221 "0201BB104KW160" 0201_cap 4430.48,278.8 r180 top value="0.1 uF"
C222 "0201BB104KW160" 0201_cap 4211.99,620.63 r0 top value="0.1 uF"
C223 "0201BB104KW160" 0201_cap 4452.53,278.8 r0 top value="0.1 uF"
C224 "0201BB104KW160" 0201_cap 4010,609.61 r90 top value="0.1 uF"
C225 "0201BB104KW160" 0201_cap 4021.02,620.63 r180 top value="0.1 uF"
C226 "GJM0335C1HR50WB01D" 0201_cap 4292.51,562.45 r0 bottom value="0.5 pF"
C227 "GJM0335C1HR50WB01D" 0201_cap 4342.51,562.45 r0 bottom value="0.5 pF"
C228 "0201BB104KW160" 0201_cap 4323.02,2112.6 r270 top value="0.1 uF"
C229 "0201BB104KW160" 0201_cap 4430.48,2445.14 r180 top value="0.1 uF"
C230 "0201BB104KW160" 0201_cap 4311.99,2101.58 r0 top value="0.1 uF"
C231 "0201BB104KW160" 0201_cap 4452.53,2445.14 r0 top value="0.1 uF"
C232 "0201BB104KW160" 0201_cap 4110,2112.6 r270 top value="0.1 uF"
C233 "0201BB104KW160" 0201_cap 4121.02,2101.58 r180 top value="0.1 uF"
C234 "GJM0335C1HR50WB01D" 0201_cap 4029.5,2200.1 r180 bottom value="0.5 pF"
C235 "GJM0335C1HR50WB01D" 0201_cap 4079.5,2200.1 r180 bottom value="0.5 pF"
C236 "GRM033Z71C104KE14D" 0201_cap 4465.72,1503.7 r315 bottom value="0.1 uF"
C237 "GRM033Z71C104KE14D" 0201_cap 4449.97,1566.69 r90 bottom value="0.1 uF"
C238 "GRM033Z71C104KE14D" 0201_cap 4403.53,1535.2 r225 bottom value="0.1 uF"
C239 "GRM033Z71C104KE14D" 0201_cap 4371.23,1535.2 r225 bottom value="0.1 uF"
C240 "GRM033Z71C104KE14D" 0201_cap 4355.48,1566.69 r90 bottom value="0.1 uF"
C241 "GRM033Z71C104KE14D" 0201_cap 4323.99,1535.2 r270 bottom value="0.1 uF"
C242 "GRM033Z71C104KE14D" 0201_cap 4292.49,1535.2 r270 bottom value="0.1 uF"
C243 "GRM033Z71C104KE14D" 0201_cap 4229.5,1472.2 r90 bottom value="0.1 uF"
C244 "GRM033Z71C104KE14D" 0201_cap 4261,1472.2 r90 bottom value="0.1 uF"
C245 "GRM033Z71C104KE14D" 0201_cap 4292.49,1472.2 r90 bottom value="0.1 uF"
C246 "GRM033Z71C104KE14D" 0201_cap 4323.99,1472.2 r90 bottom value="0.1 uF"
C247 "GRM033Z71C104KE14D" 0201_cap 4371.23,1487.95 r180 bottom value="0.1 uF"
C248 "GRM033Z71C104KE14D" 0201_cap 4371.23,1456.46 r180 bottom value="0.1 uF"
C249 "GRM033Z71C104KE14D" 0201_cap 4371.23,1424.96 r0 bottom value="0.1 uF"
C250 "GRM033Z71C104KE14D" 0201_cap 4434.22,1456.46 r180 bottom value="0.1 uF"
C251 "GRM033Z71C104KE14D" 0201_cap 4465.72,1409.21 r315 bottom value="0.1 uF"
C252 "GRM033Z71C104KE14D" 0201_cap 4418.48,1409.21 r270 bottom value="0.1 uF"
C253 "GRM033Z71C104KE14D" 0201_cap 4229.5,1409.21 r270 bottom value="0.1 uF"
C254 "GRM033Z71C104KE14D" 0201_cap 4261,1409.21 r90 bottom value="0.1 uF"
C255 "GRM033Z71C104KE14D" 0201_cap 4292.49,1409.21 r270 bottom value="0.1 uF"
C256 "GRM033Z71C104KE14D" 0201_cap 4323.99,1409.21 r90 bottom value="0.1 uF"
C257 "GRM033Z71C104KE14D" 0201_cap 4371.23,1393.46 r180 bottom value="0.1 uF"
C258 "GRM033Z71C104KE14D" 0201_cap 4261,1346.22 r90 bottom value="0.1 uF"
C259 "GRM033Z71C104KE14D" 0201_cap 4292.49,1346.22 r270 bottom value="0.1 uF"
C260 "GRM033Z71C104KE14D" 0201_cap 4323.99,1346.22 r90 bottom value="0.1 uF"
C261 "GRM033Z71C104KE14D" 0201_cap 4355.48,1346.22 r270 bottom value="0.1 uF"
C262 "GRM033Z71C104KE14D" 0201_cap 4386.98,1346.22 r90 bottom value="0.1 uF"
C263 "GRM033Z71C104KE14D" 0201_cap 4418.48,1346.22 r270 bottom value="0.1 uF"
C264 "GRM033Z71C104KE14D" 0201_cap 4229.5,1314.72 r90 bottom value="0.1 uF"
C265 "GRM033Z71C104KE14D" 0201_cap 4276.74,1298.98 r180 bottom value="0.1 uF"
C266 "GRM033Z71C104KE14D" 0201_cap 4339.74,1298.98 r180 bottom value="0.1 uF"
C267 "GRM033Z71C104KE14D" 0201_cap 4402.73,1298.98 r180 bottom value="0.1 uF"
C268 "GRM033Z71C104KE14D" 0201_cap 4229.5,1251.73 r270 bottom value="0.1 uF"
C269 "GRM033Z71C104KE14D" 0201_cap 4261,1251.73 r270 bottom value="0.1 uF"
C270 "GRM033Z71C104KE14D" 0201_cap 4292.49,1251.73 r270 bottom value="0.1 uF"
C271 "GRM033Z71C104KE14D" 0201_cap 4323.99,1251.73 r270 bottom value="0.1 uF"
C272 "GRM033Z71C104KE14D" 0201_cap 4371.23,1267.48 r180 bottom value="0.1 uF"
C273 "GRM033Z71C104KE14D" 0201_cap 4276.74,1157.24 r225 bottom value="0.1 uF"
C274 "GRM033Z71C104KE14D" 0201_cap 4465.72,1220.24 r45 bottom value="0.1 uF"
C275 "GRM033Z71C104KE14D" 0201_cap 4465.72,1157.24 r315 bottom value="0.1 uF"
C276 "GRM033Z71C104KE14D" 0201_cap 4198,1314.72 r270 bottom value="0.1 uF"
C277 "GRM033Z71C104KE14D" 0201_cap 4198,1251.73 r270 bottom value="0.1 uF"
C278 "GRM033Z71C104KE14D" 0201_cap 4198,1472.2 r90 bottom value="0.1 uF"
C279 "GRM033Z71C104KE14D" 0201_cap 4198,1409.21 r90 bottom value="0.1 uF"
C280 "GRM033Z71C104KE14D" 0201_cap 4212.75,1157.24 r225 bottom value="0.1 uF"
C281 "GRM033Z71C104KE14D" 0201_cap 4244.75,1157.24 r225 bottom value="0.1 uF"
C282 "GRM033Z71C104KE14D" 0201_cap 4103.52,1377.72 r90 bottom value="0.1 uF"
C283 "GRM033Z71C104KE14D" 0201_cap 4119.26,1346.22 r225 bottom value="0.1 uF"
C284 "GRM033Z71C104KE14D" 0201_cap 4402.73,1503.7 r135 bottom value="0.1 uF"
C285 "GRM033Z71C104KE14D" 0201_cap 4087.77,1298.98 r180 bottom value="0.1 uF"
C286 "GRM033Z71C104KE14D" 0201_cap 4087.77,1267.48 r180 bottom value="0.1 uF"
C287 "GRM033Z71C104KE14D" 0201_cap 4040.52,1440.71 r90 bottom value="0.1 uF"
C288 "GRM033Z71C104KE14D" 0201_cap 4024.78,1409.21 r315 bottom value="0.1 uF"
C289 "GRM033Z71C104KE14D" 0201_cap 4040.52,1283.23 r270 bottom value="0.1 uF"
C290 "GRM033Z71C104KE14D" 0201_cap 4009.03,1283.23 r270 bottom value="0.1 uF"
C291 "GRM033Z71C104KE14D" 0201_cap 4087.77,1424.96 r180 bottom value="0.1 uF"
C292 "GRM033Z71C104KE14D" 0201_cap 4087.77,1456.46 r180 bottom value="0.1 uF"
C293 "GRM033Z71C104KE14D" 0201_cap 4229.5,1350.94 r270 bottom value="0.1 uF"
C294 "GRM033Z71C104KE14D" 0201_cap 4103.52,1566.67 r90 bottom value="0.1 uF"
C295 "GRM033Z71C104KE14D" 0201_cap 4135.01,1566.67 r90 bottom value="0.1 uF"
C296 "GRM033Z71C104KE14D" 0201_cap 4166.51,1566.67 r90 bottom value="0.1 uF"
C297 "GRM033Z71C104KE14D" 0201_cap 4182.24,1519.45 r0 bottom value="0.1 uF"
C298 "GRM033Z71C104KE14D" 0201_cap 4119.51,1503.7 r225 bottom value="0.1 uF"
C299 "GRM033Z71C104KE14D" 0201_cap 4087.52,1503.7 r225 bottom value="0.1 uF"
C300 "GRM033Z71C104KE14D" 0201_cap 4103.52,1157.24 r270 bottom value="0.1 uF"
C301 "GRM033Z71C104KE14D" 0201_cap 4135.01,1157.24 r270 bottom value="0.1 uF"
C302 "GRM033Z71C104KE14D" 0201_cap 4166.51,1157.24 r270 bottom value="0.1 uF"
C303 "GRM033Z71C104KE14D" 0201_cap 4182.26,1204.49 r0 bottom value="0.1 uF"
C304 "GRM033Z71C104KE14D" 0201_cap 4119.26,1220.24 r135 bottom value="0.1 uF"
C305 "GRM033Z71C104KE14D" 0201_cap 4087.77,1204.49 r180 bottom value="0.1 uF"
C306 "GRM033Z71C104KE14D" 0201_cap 4150.76,1487.95 r0 bottom value="0.1 uF"
C307 "GRM033Z71C104KE14D" 0201_cap 4150.76,1456.46 r180 bottom value="0.1 uF"
C308 "GRM033Z71C104KE14D" 0201_cap 4150.76,1424.96 r0 bottom value="0.1 uF"
C309 "GRM033Z71C104KE14D" 0201_cap 4150.76,1393.46 r180 bottom value="0.1 uF"
C310 "GRM033Z71C104KE14D" 0201_cap 4182.26,1361.97 r180 bottom value="0.1 uF"
C311 "GRM033Z71C104KE14D" 0201_cap 4150.76,1330.47 r180 bottom value="0.1 uF"
C312 "GRM033Z71C104KE14D" 0201_cap 4150.76,1298.98 r0 bottom value="0.1 uF"
C313 "GRM033Z71C104KE14D" 0201_cap 4150.76,1267.48 r180 bottom value="0.1 uF"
